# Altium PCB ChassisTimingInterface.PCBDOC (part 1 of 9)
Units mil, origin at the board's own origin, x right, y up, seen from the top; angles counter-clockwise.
Board outline 7007.87 x 4368.85 mil, 10 copper layers (Top Layer, Int1 (GND), Int2 (Sign), Int3 (Sign), Int4 (PWR), Int5 (GND), Int6 (Sign), Int7 (Sign), Int8 (GND), Bottom Layer), stack 54.89 mil thick; 537 components, 525 nets, 2288 pads, 1306 vias.
Unrouted connection lines stored in the file: 373.
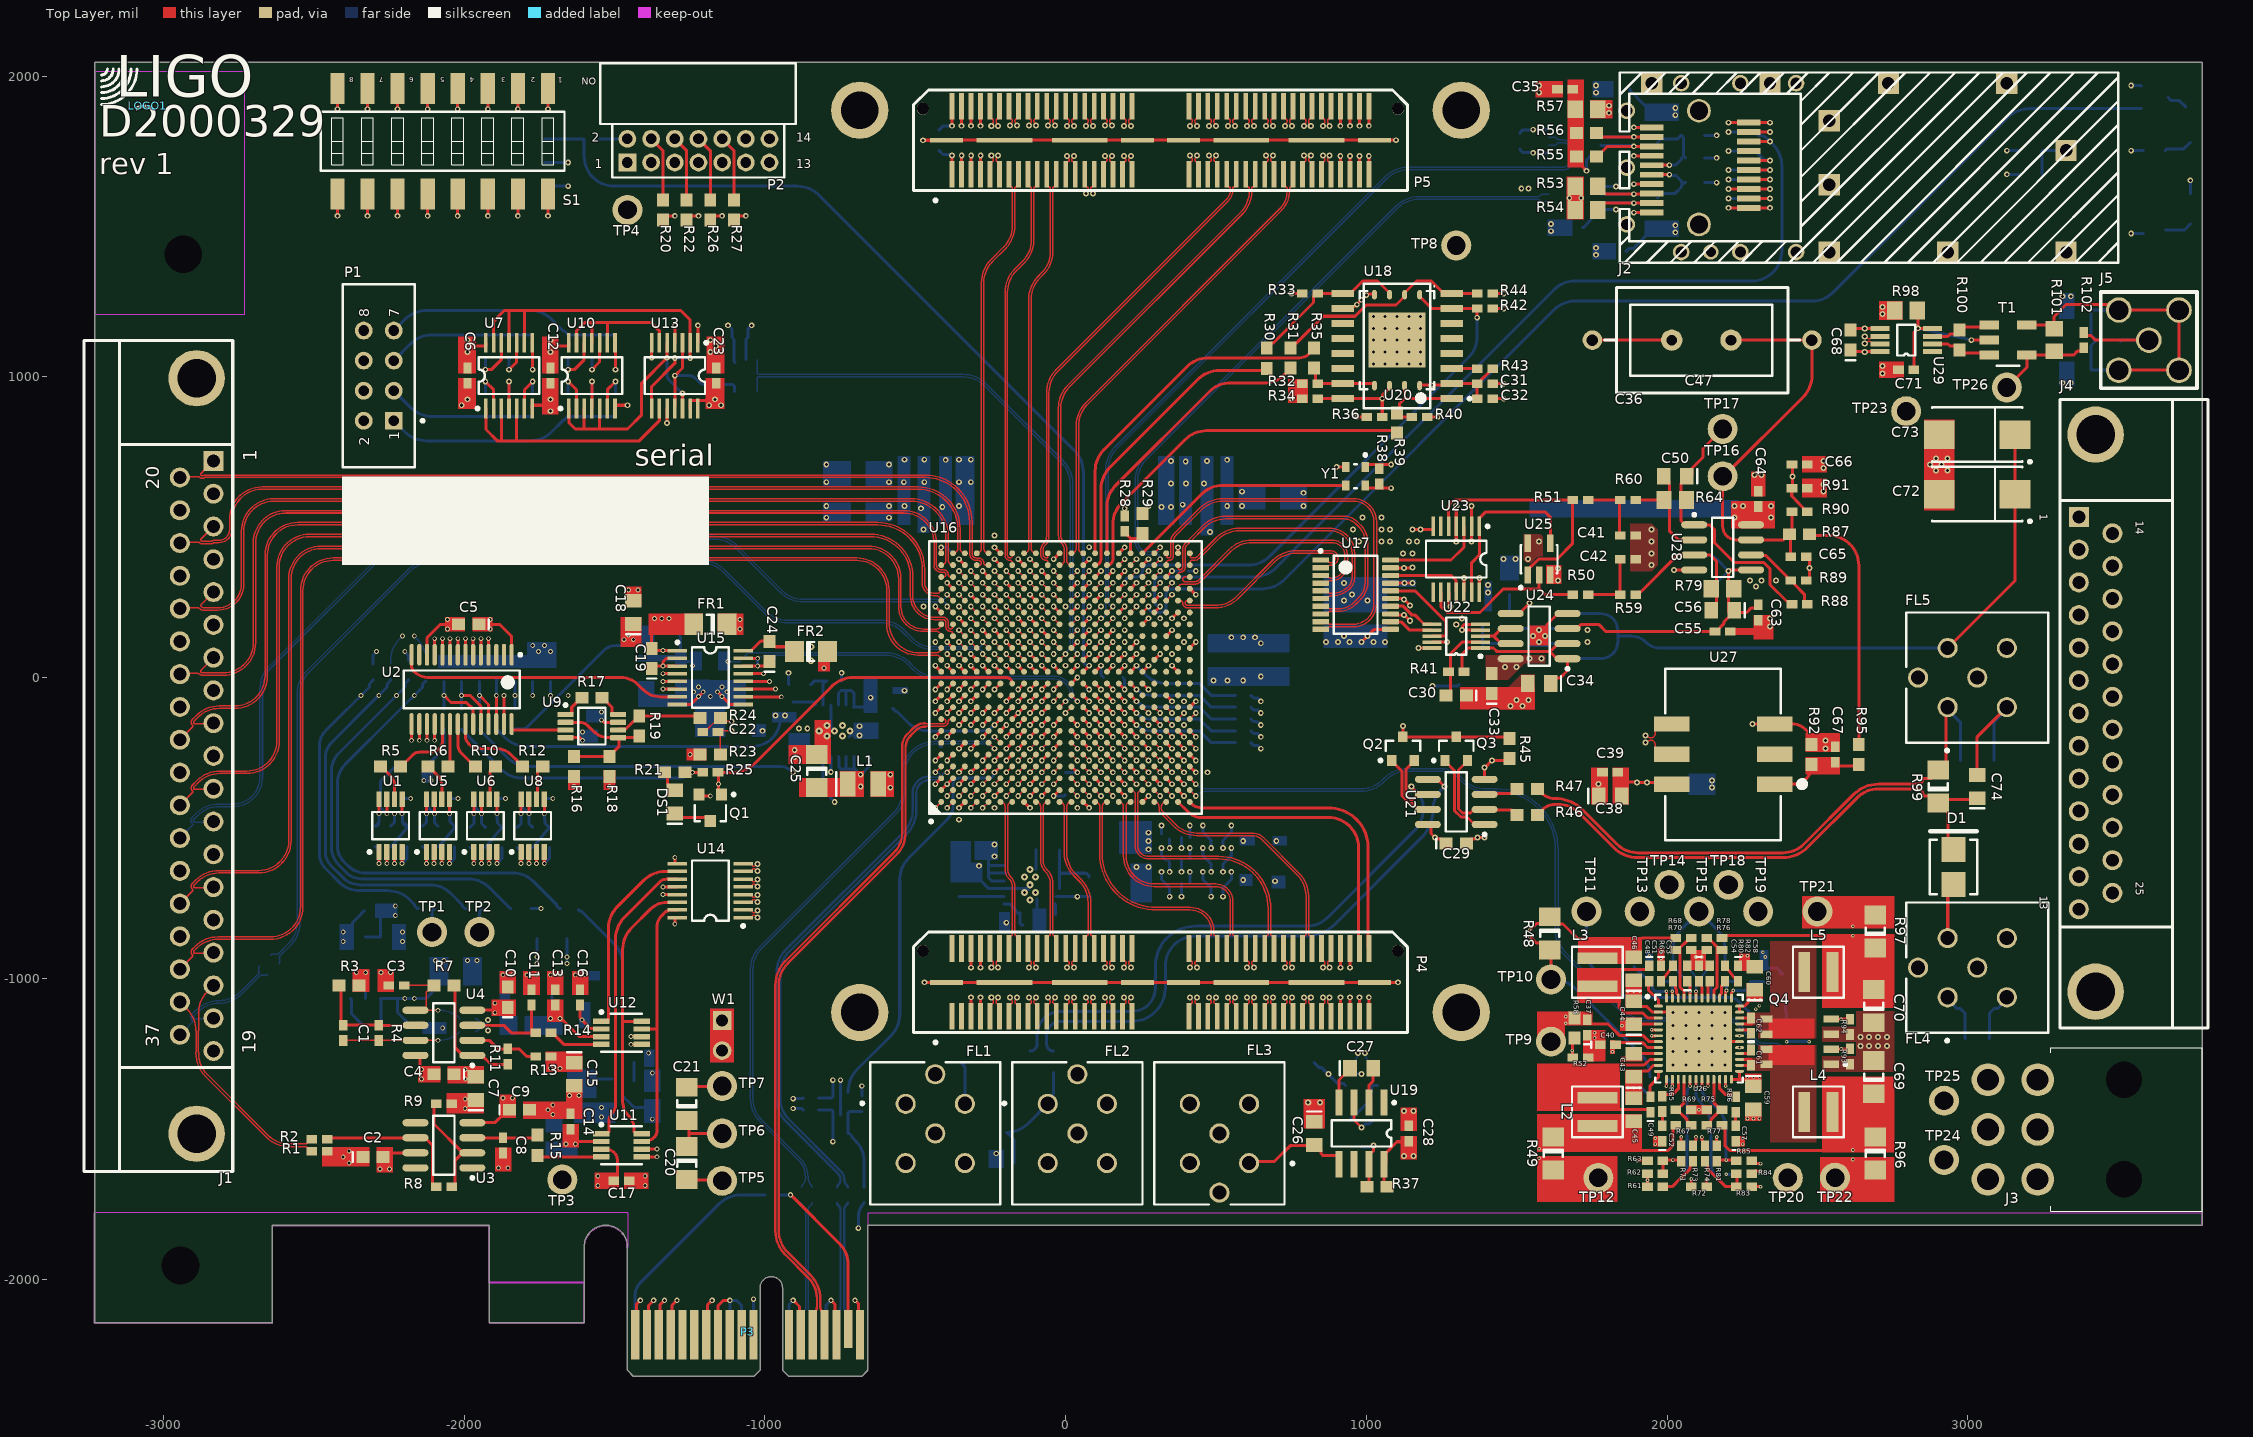
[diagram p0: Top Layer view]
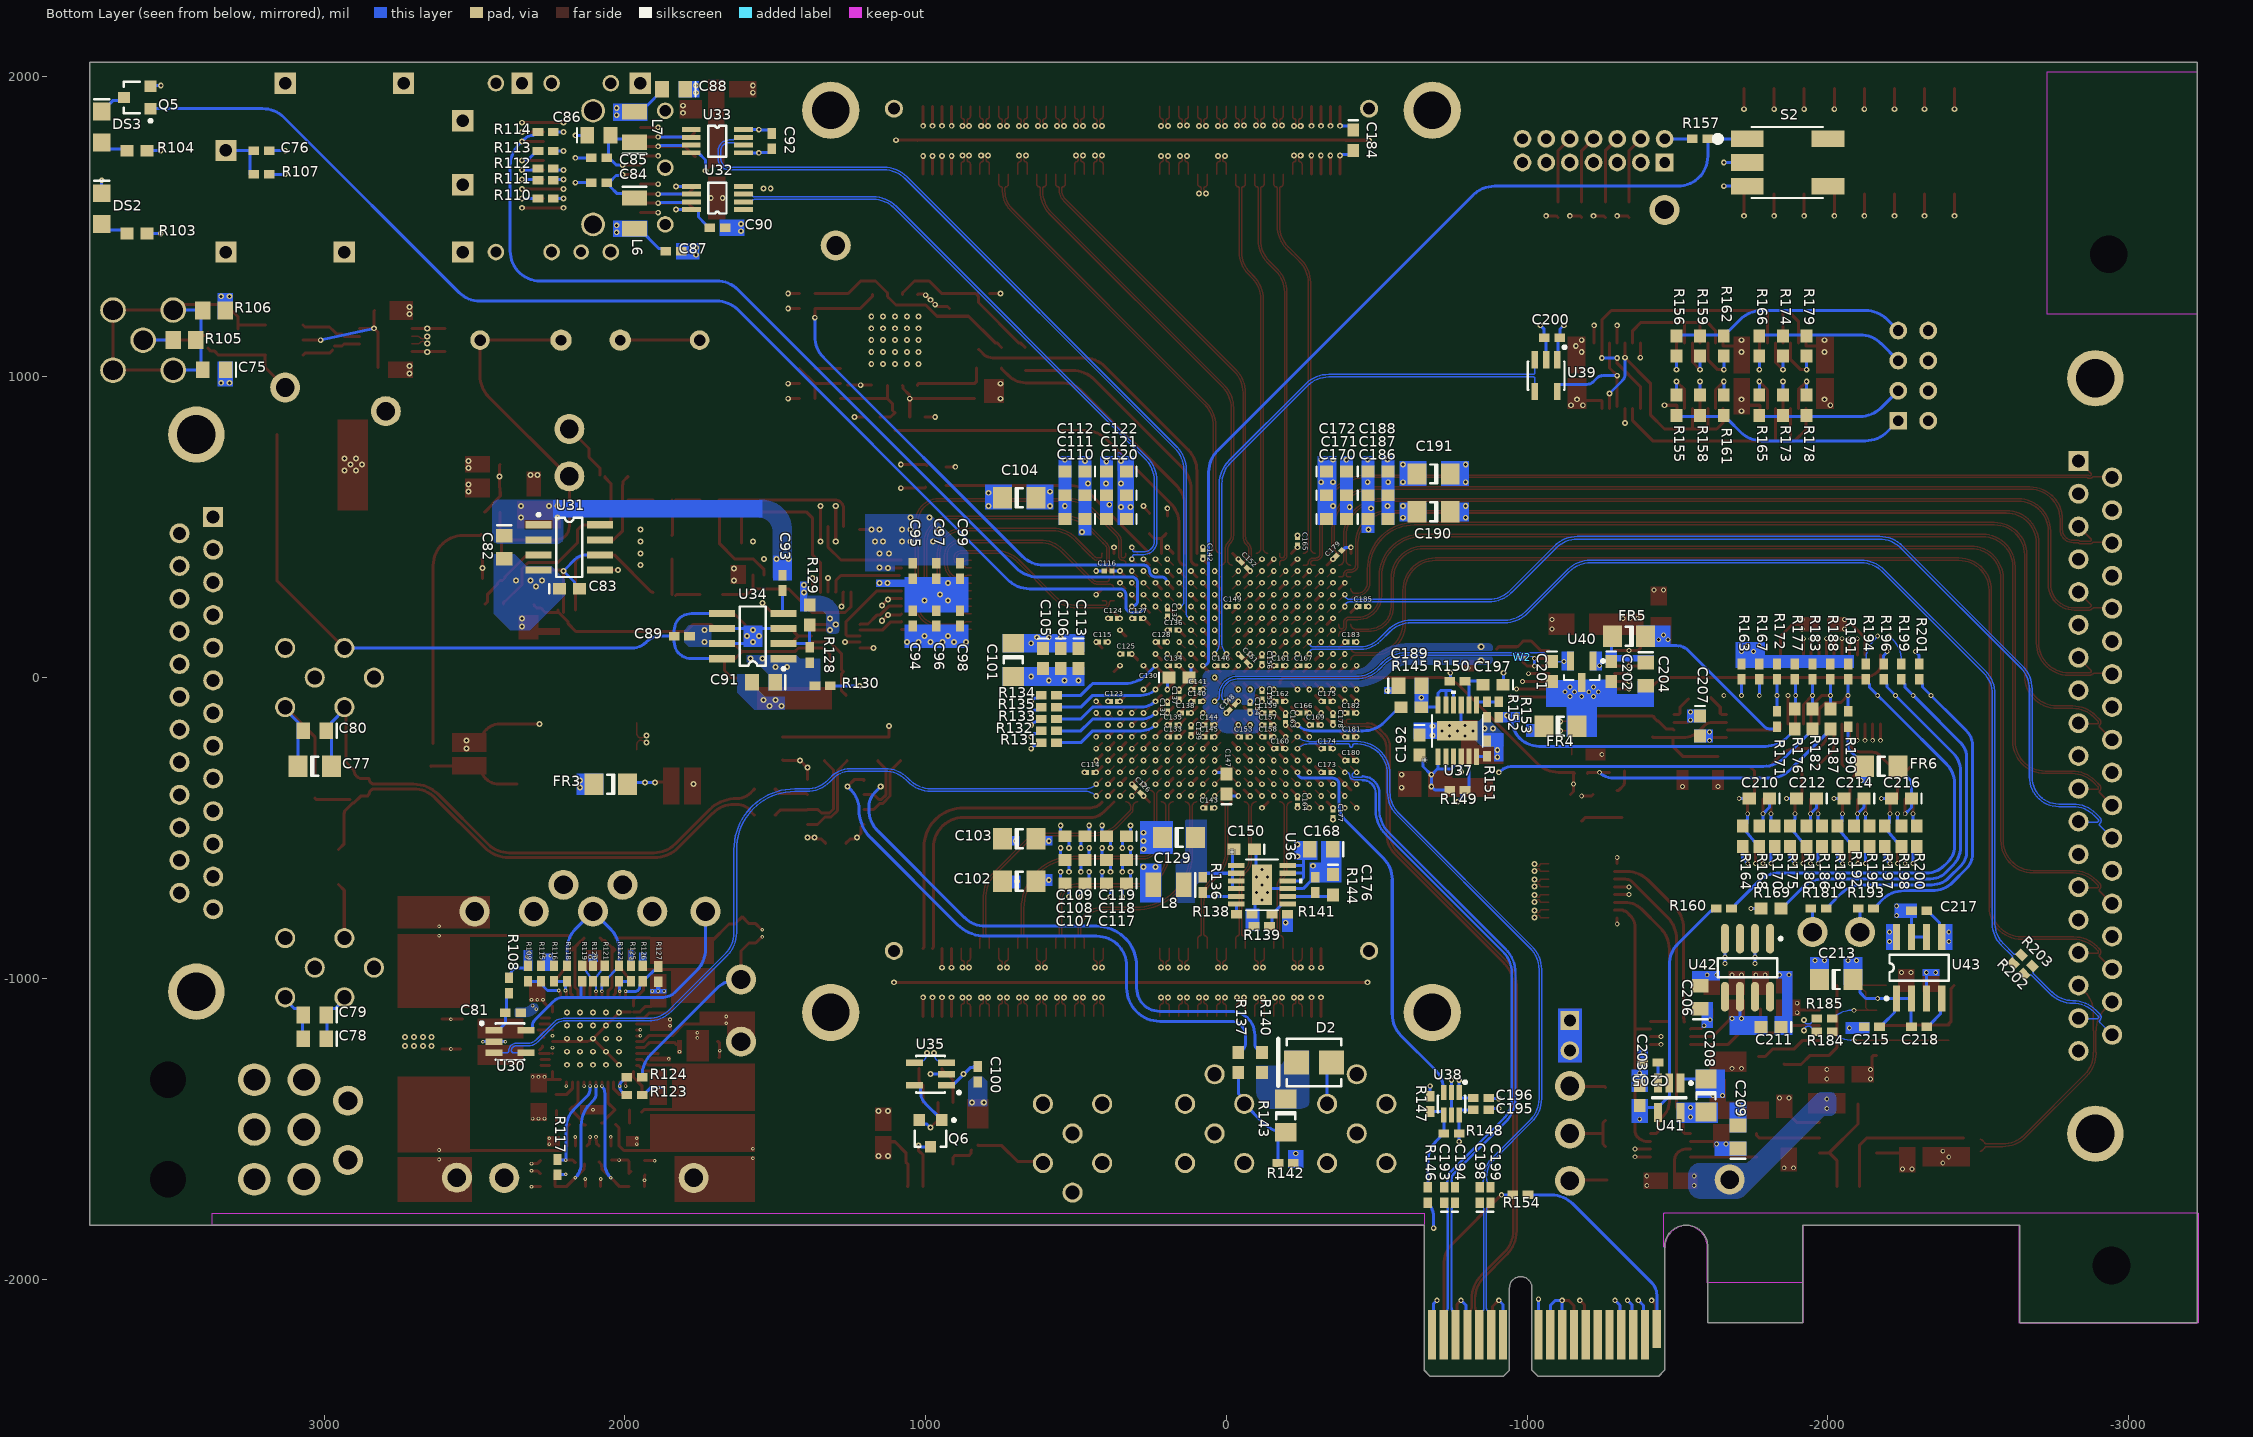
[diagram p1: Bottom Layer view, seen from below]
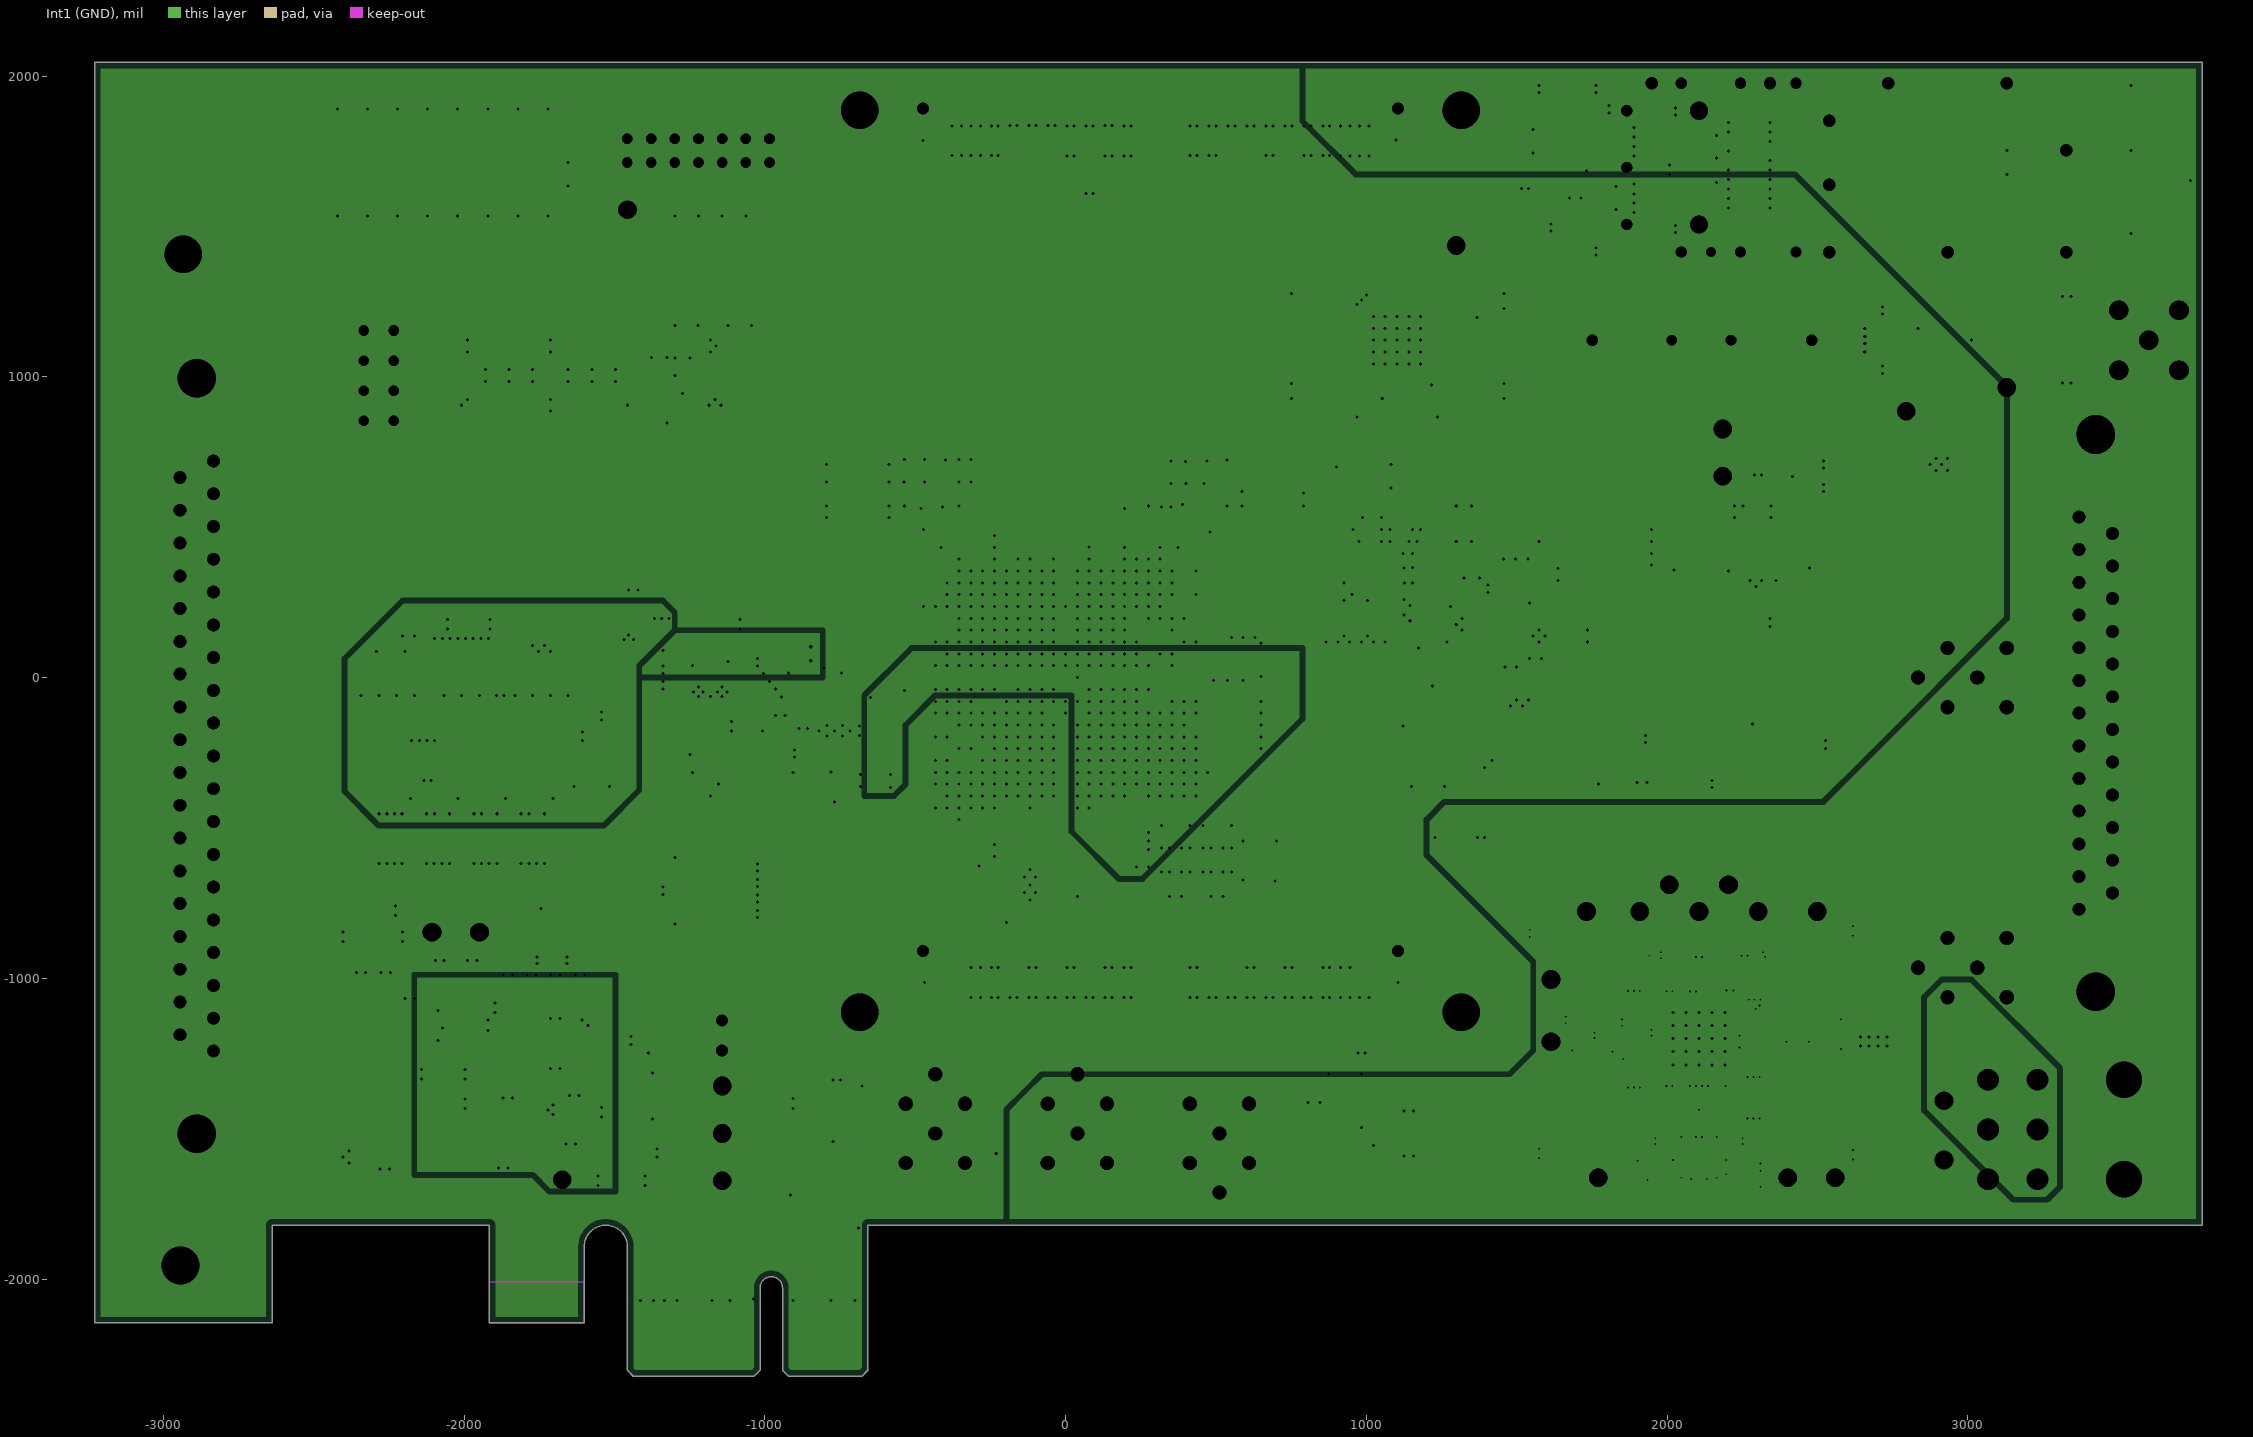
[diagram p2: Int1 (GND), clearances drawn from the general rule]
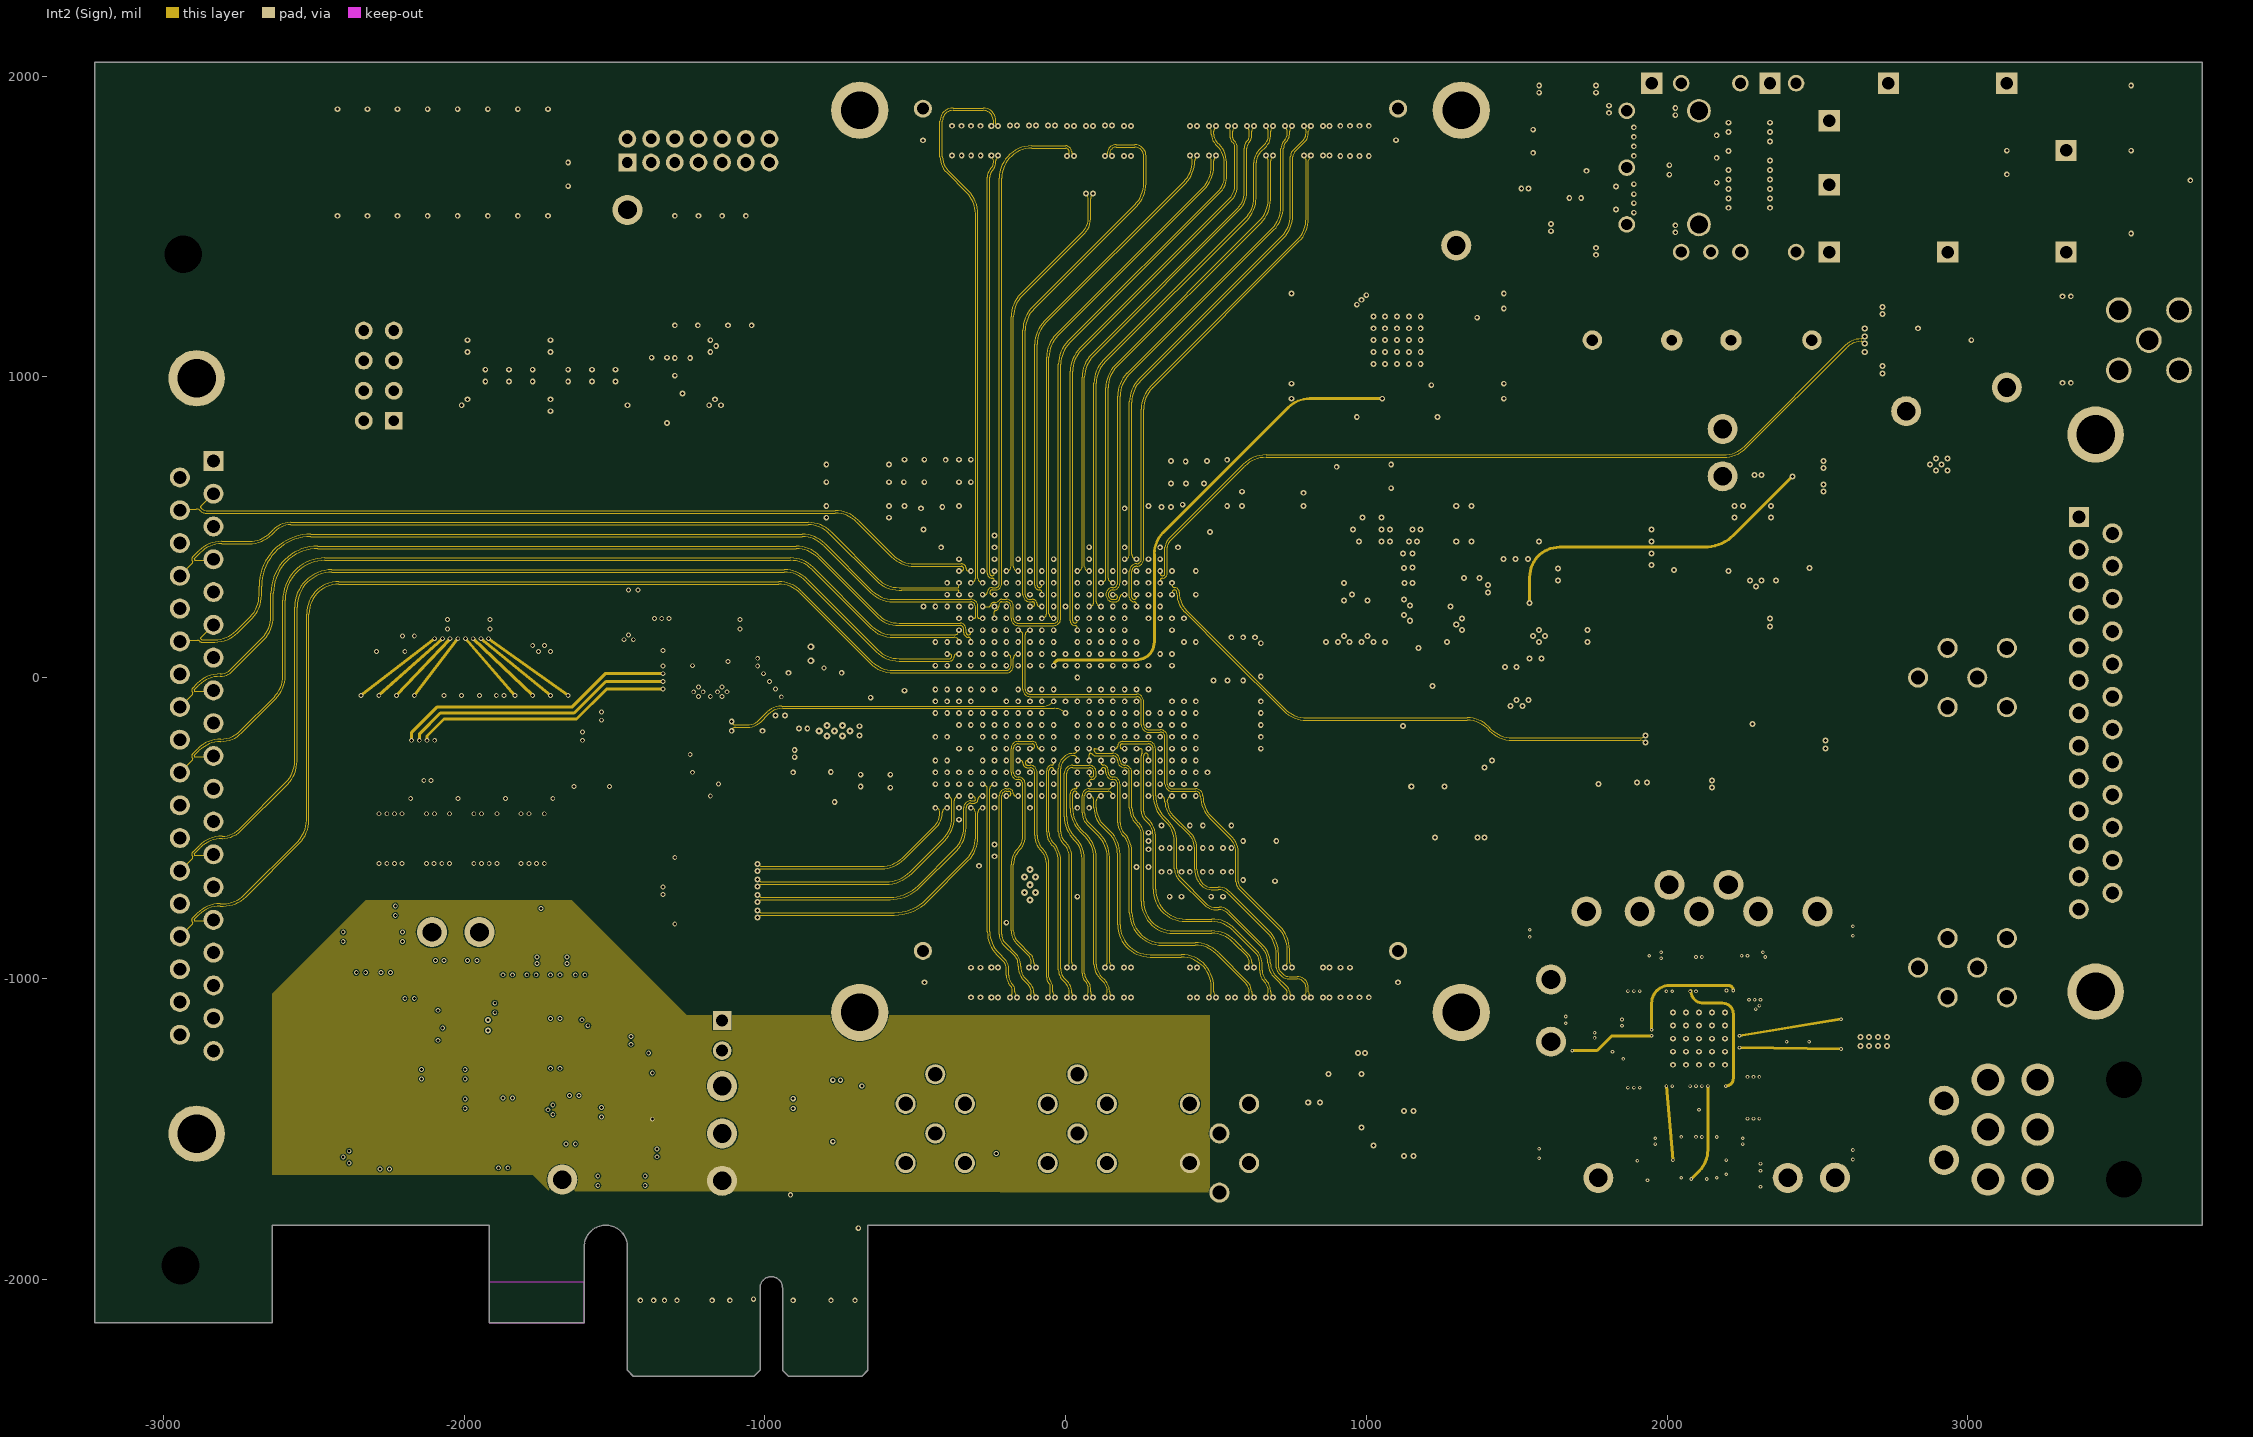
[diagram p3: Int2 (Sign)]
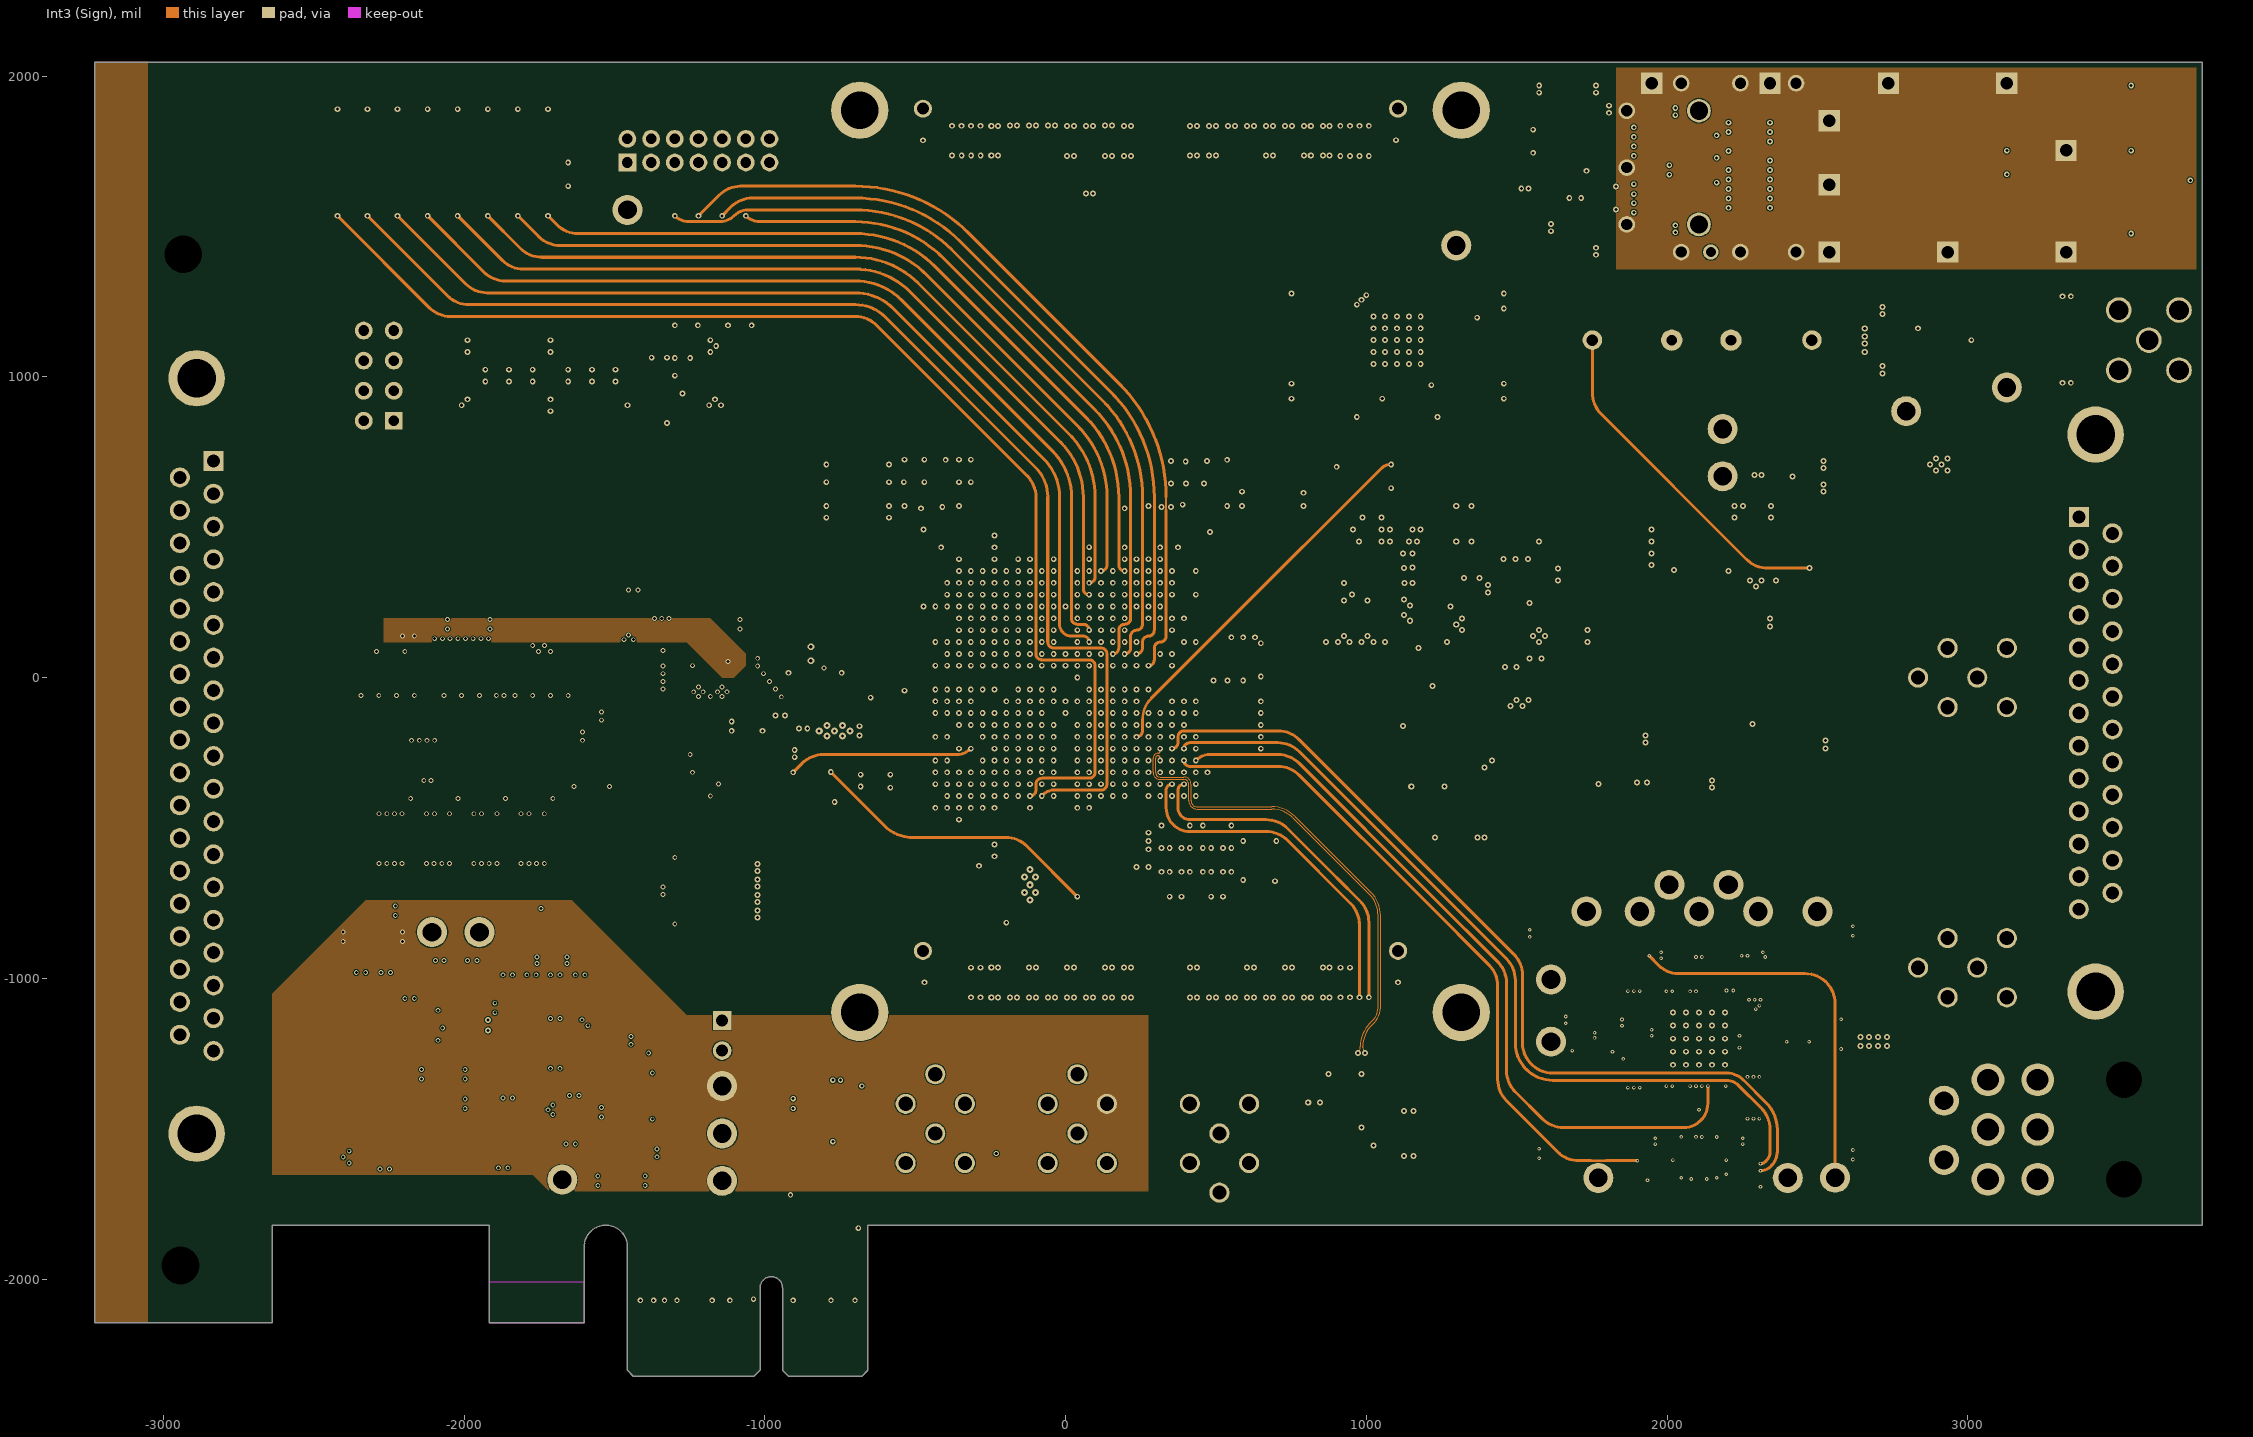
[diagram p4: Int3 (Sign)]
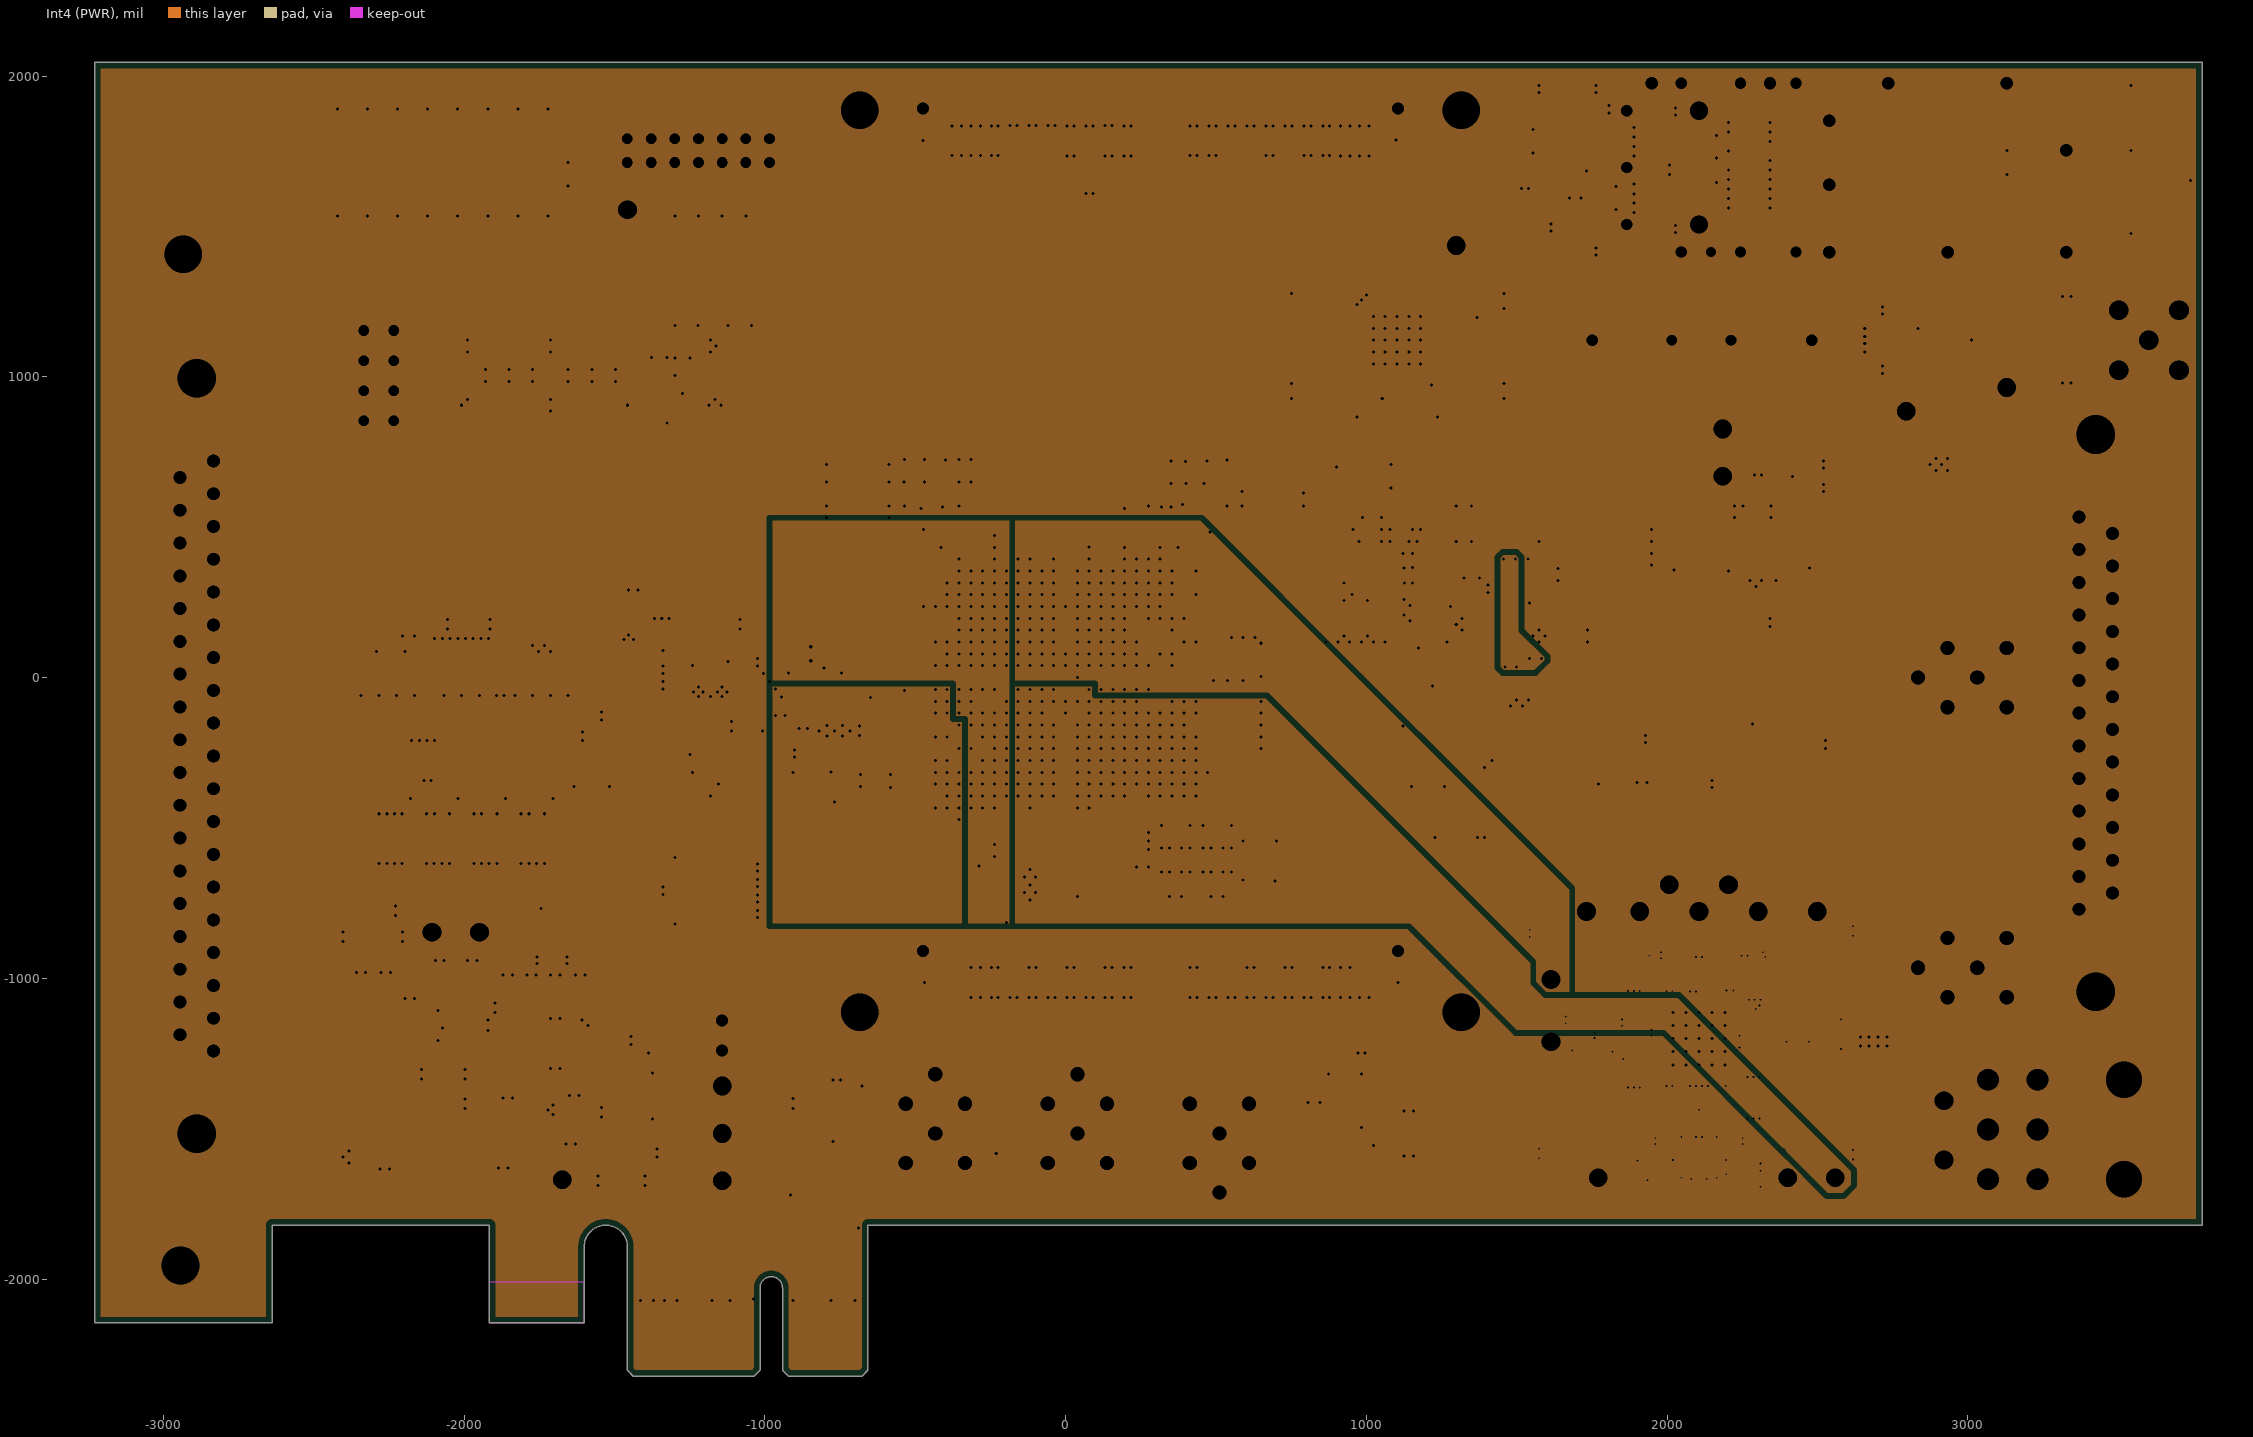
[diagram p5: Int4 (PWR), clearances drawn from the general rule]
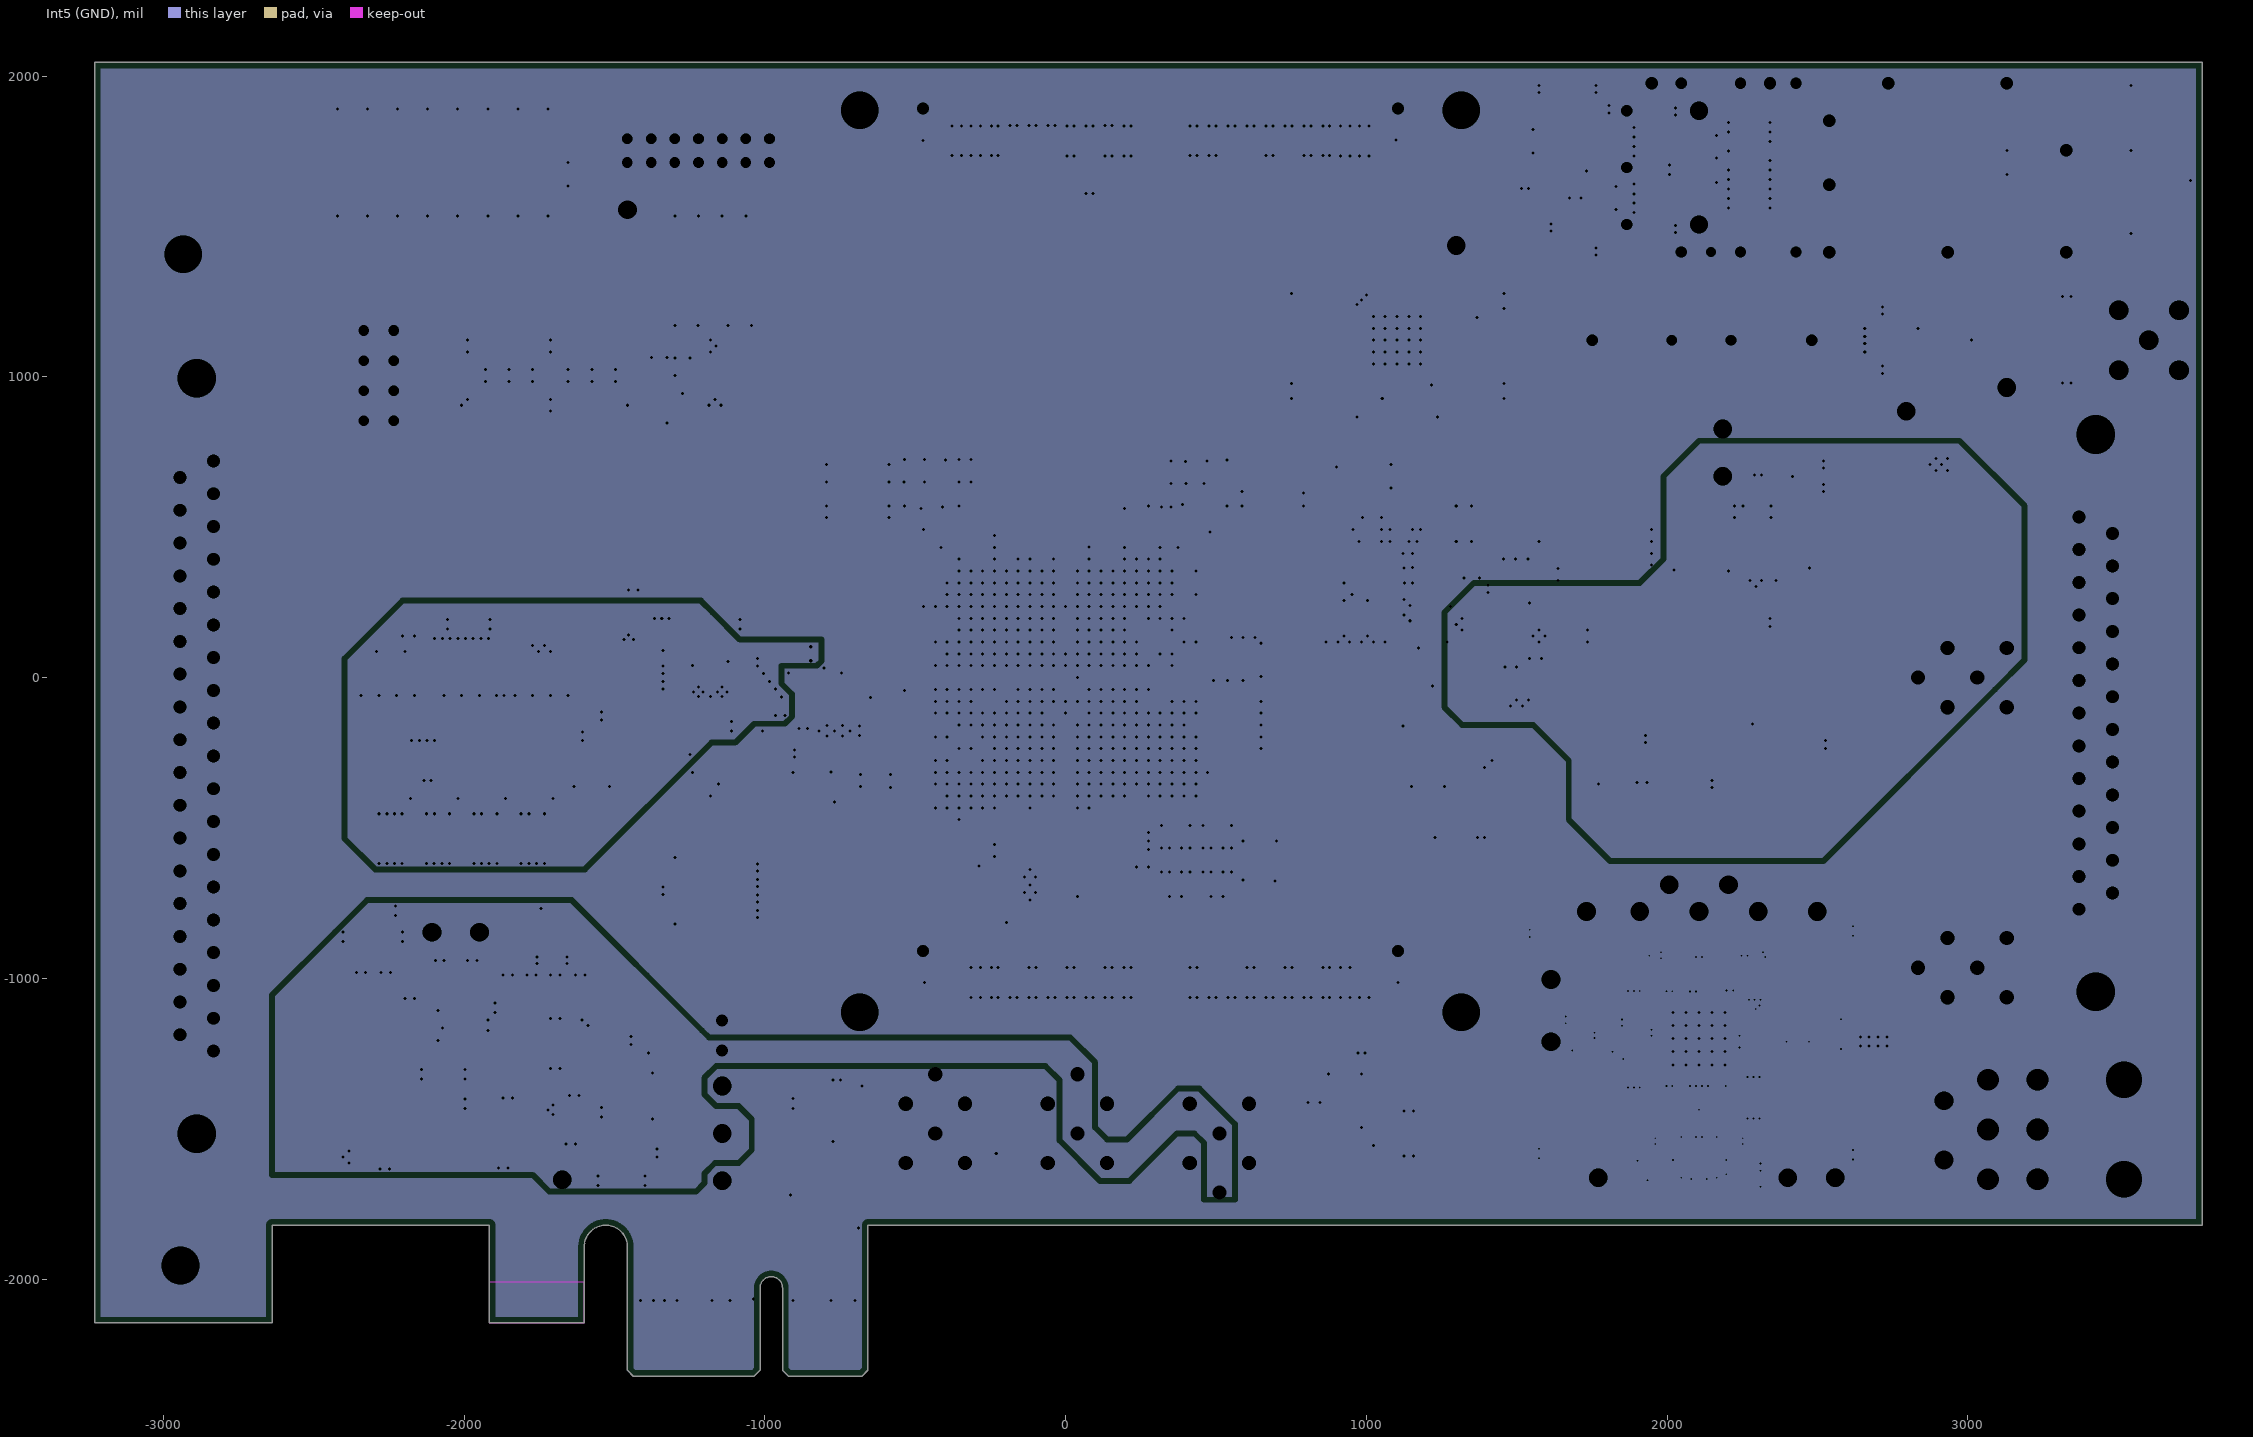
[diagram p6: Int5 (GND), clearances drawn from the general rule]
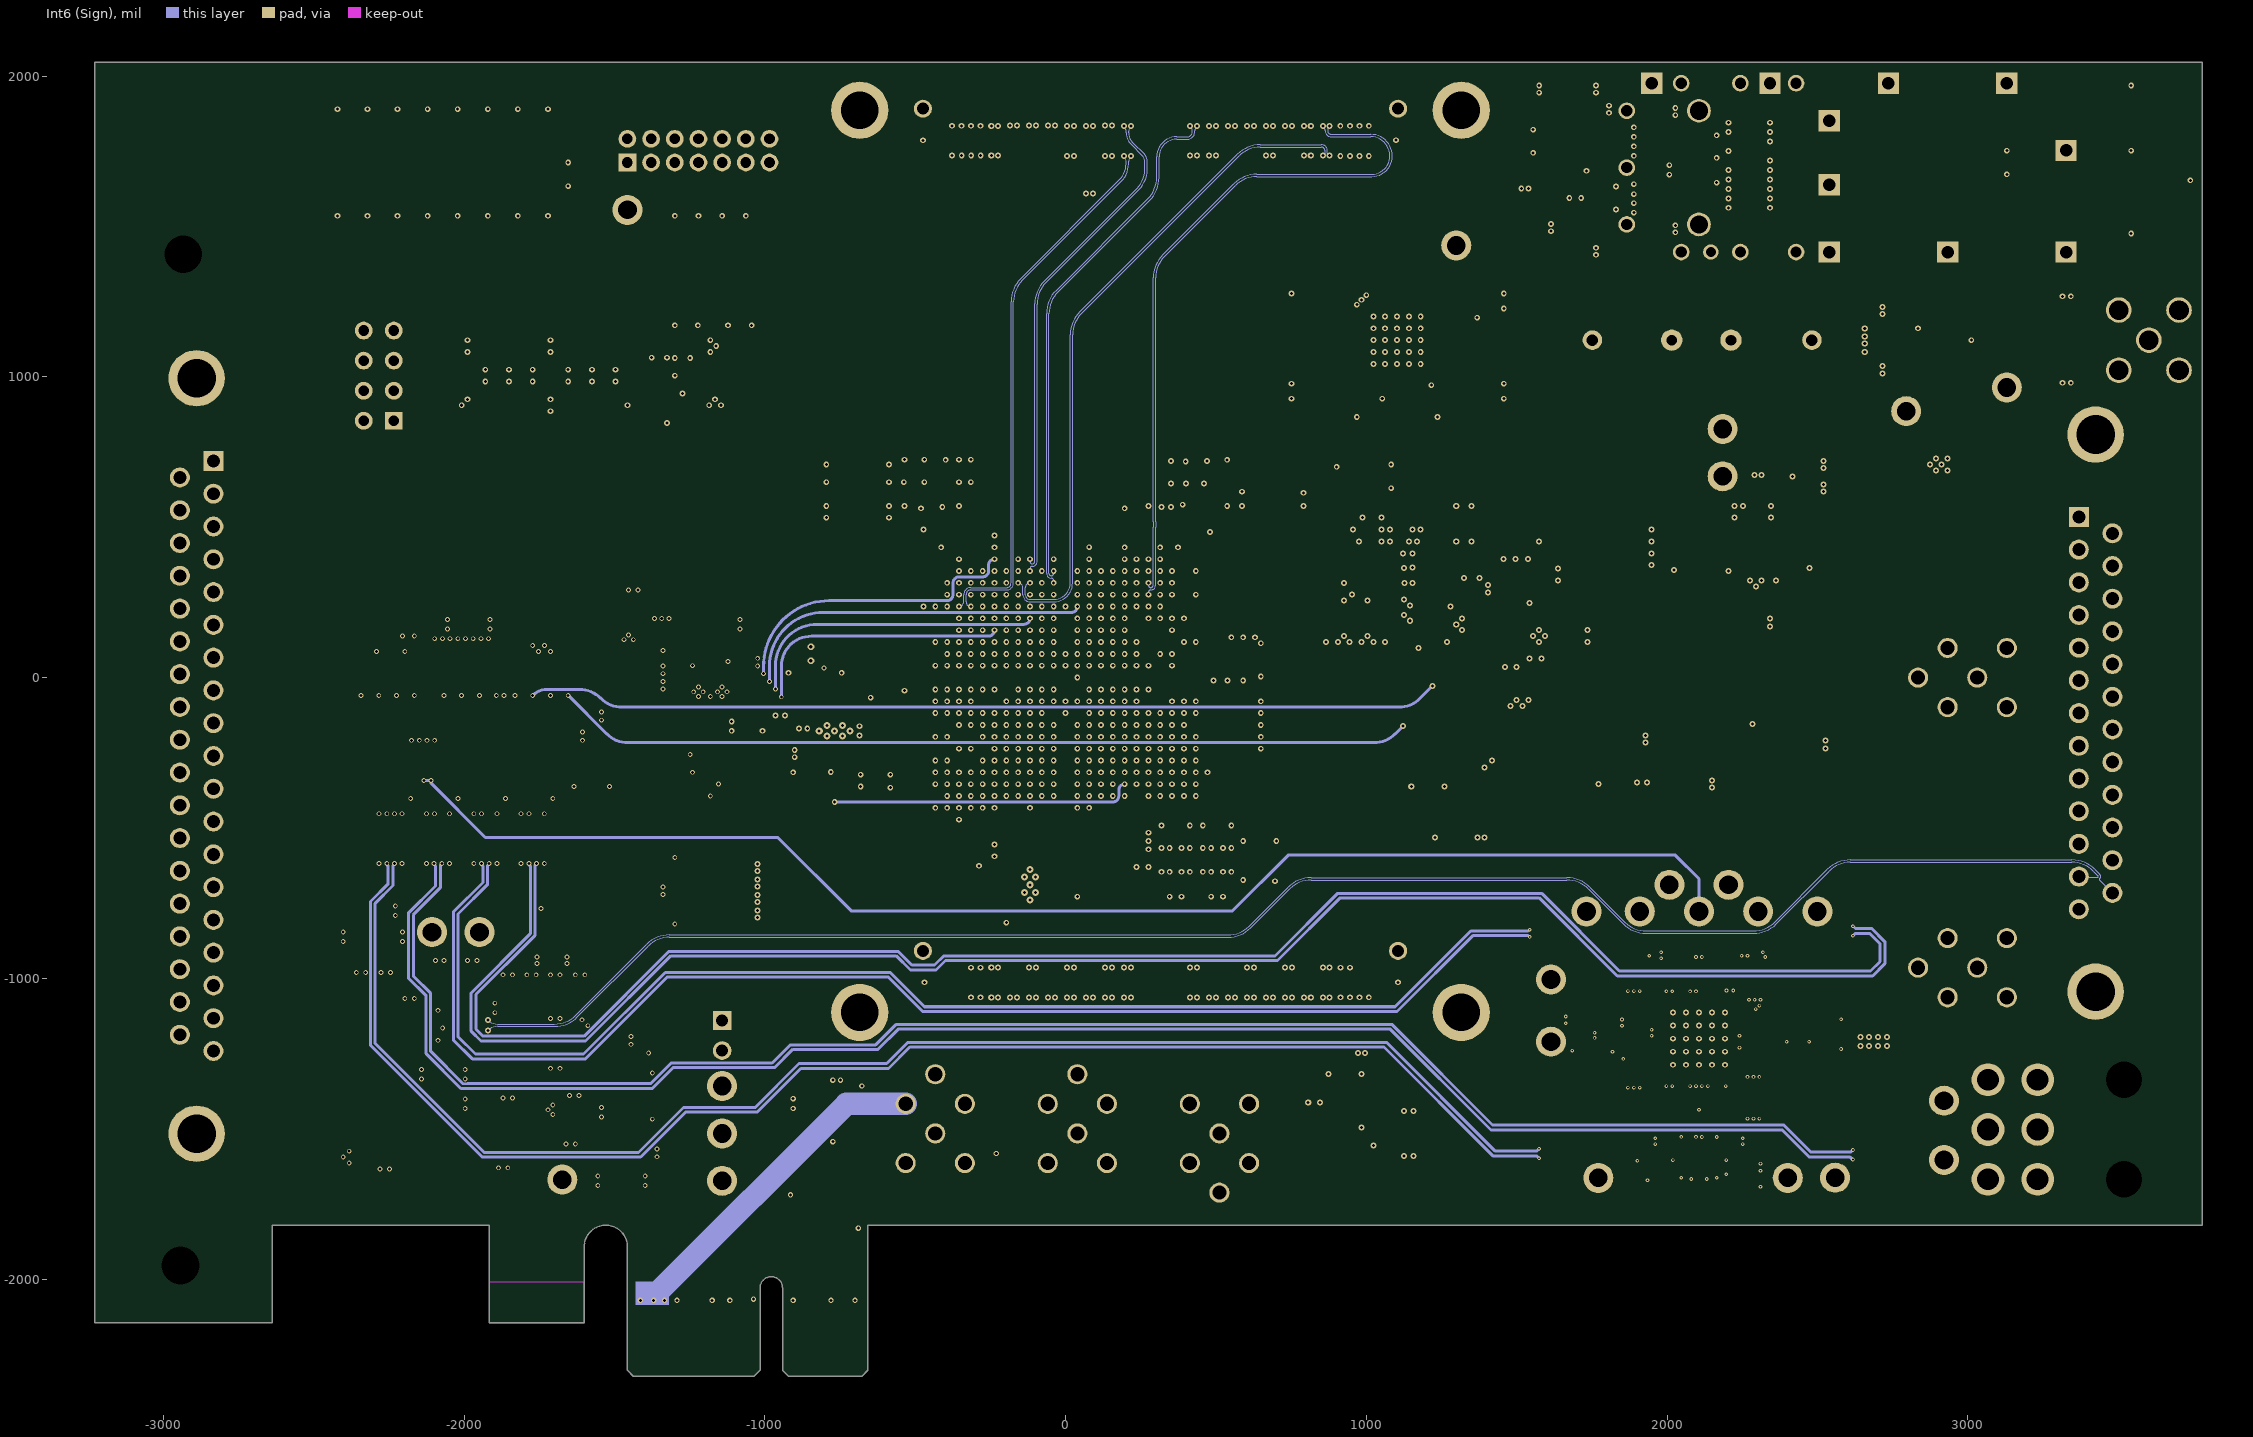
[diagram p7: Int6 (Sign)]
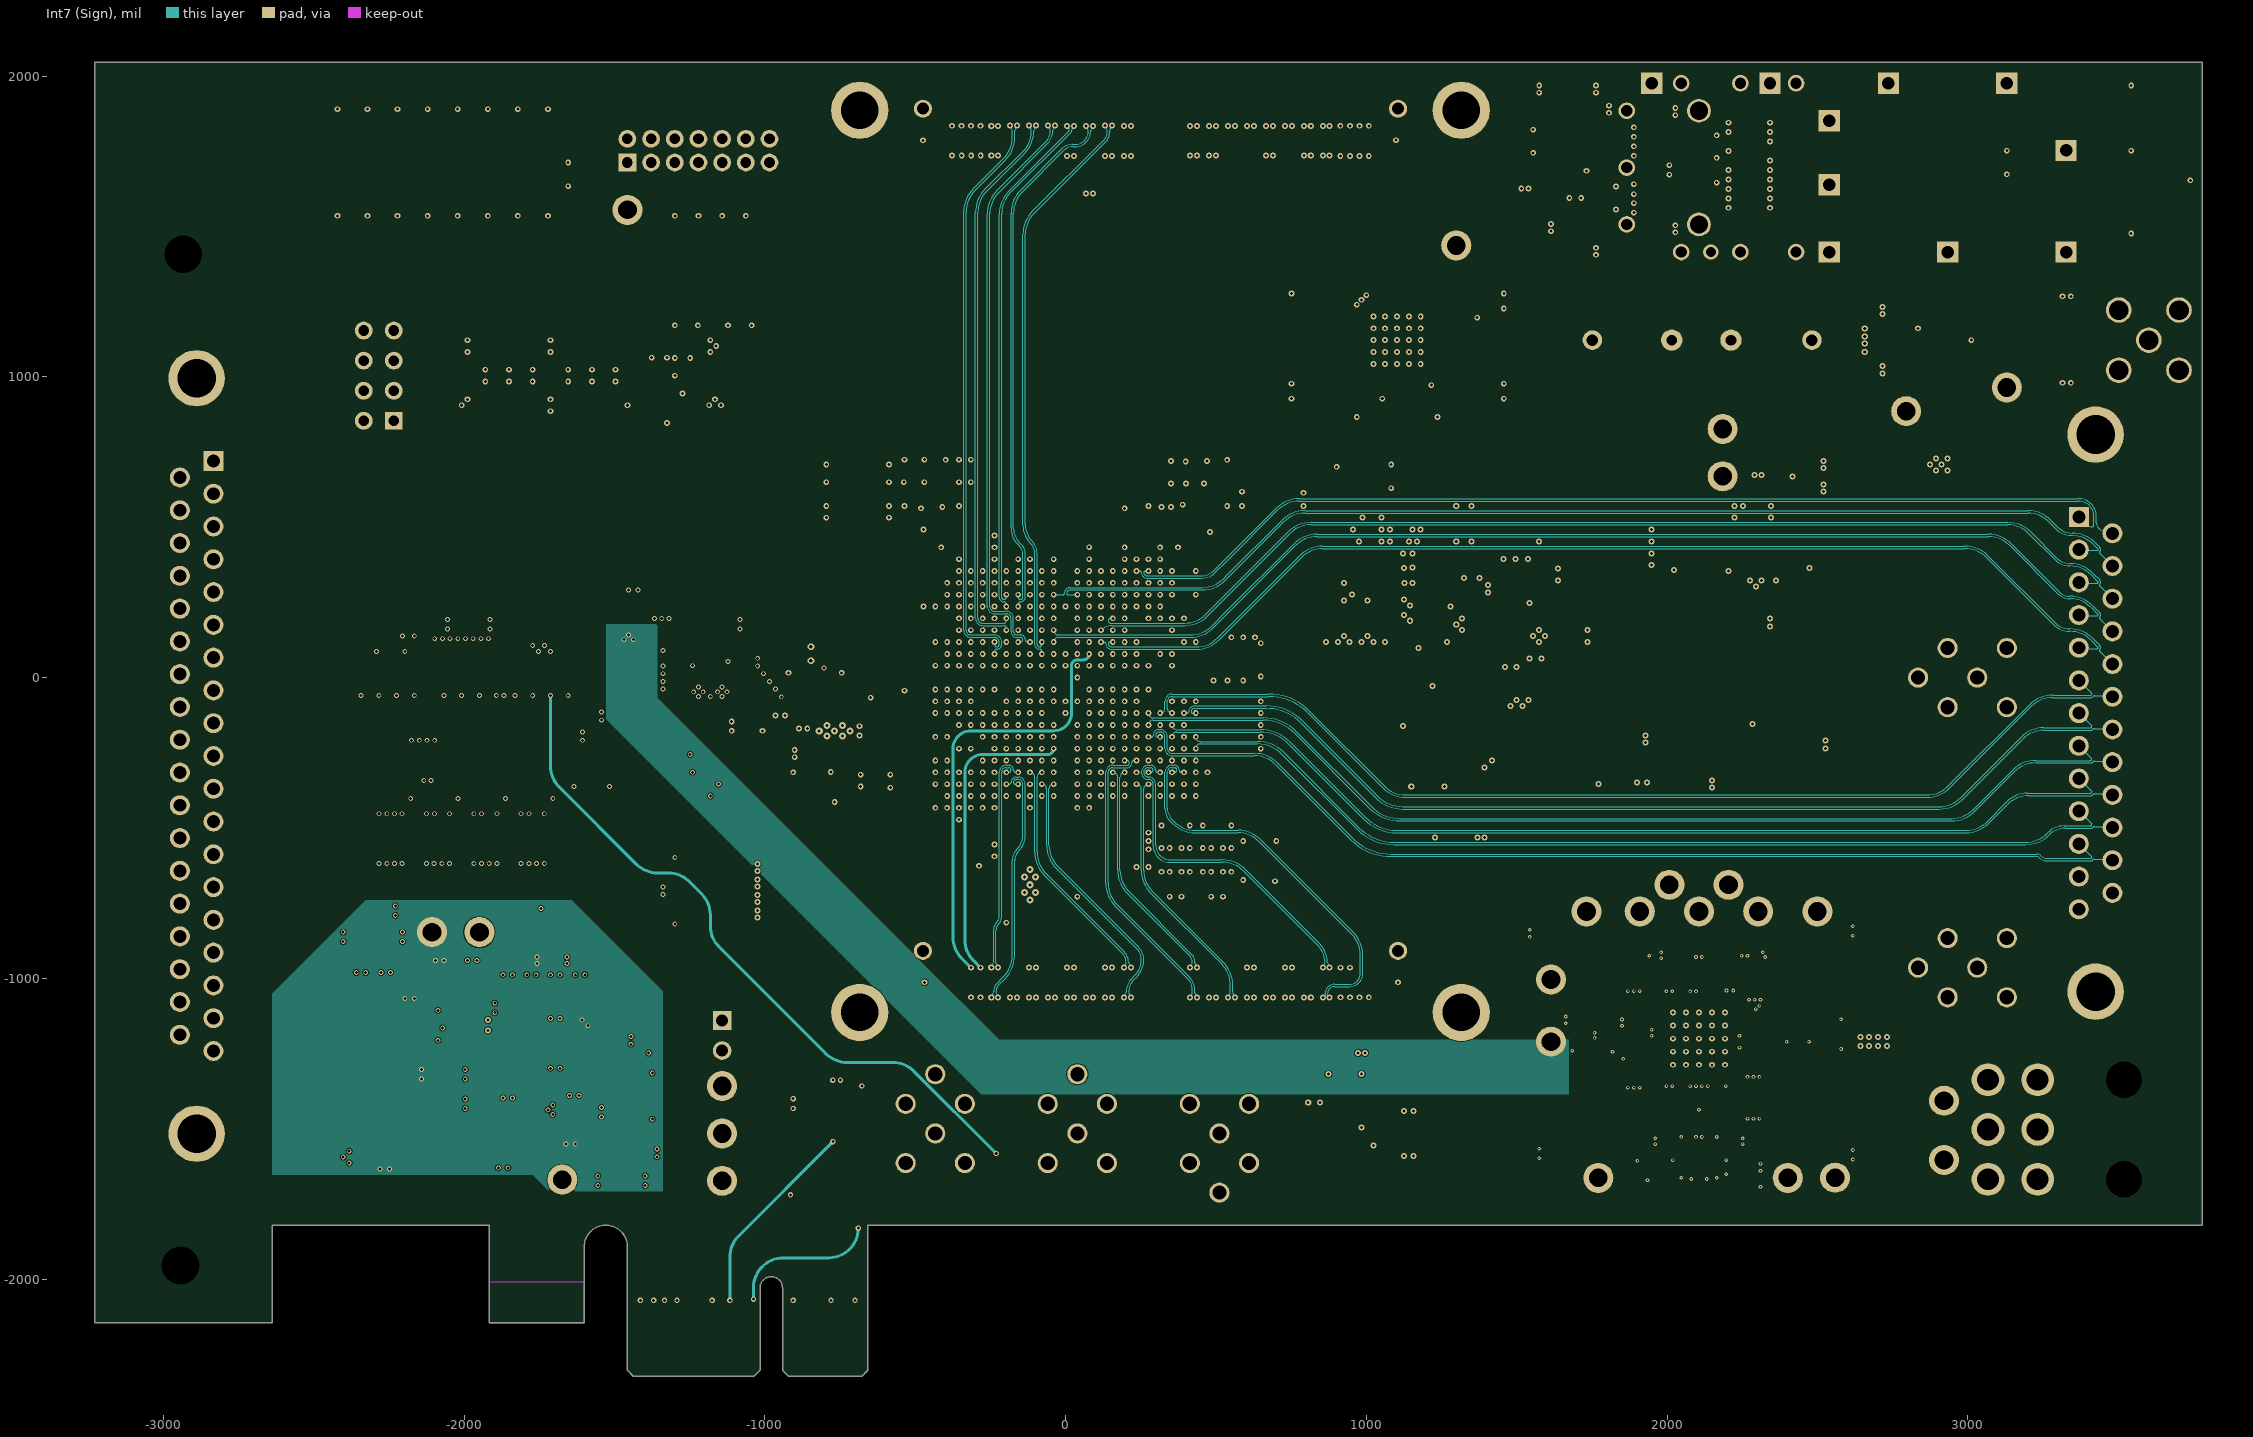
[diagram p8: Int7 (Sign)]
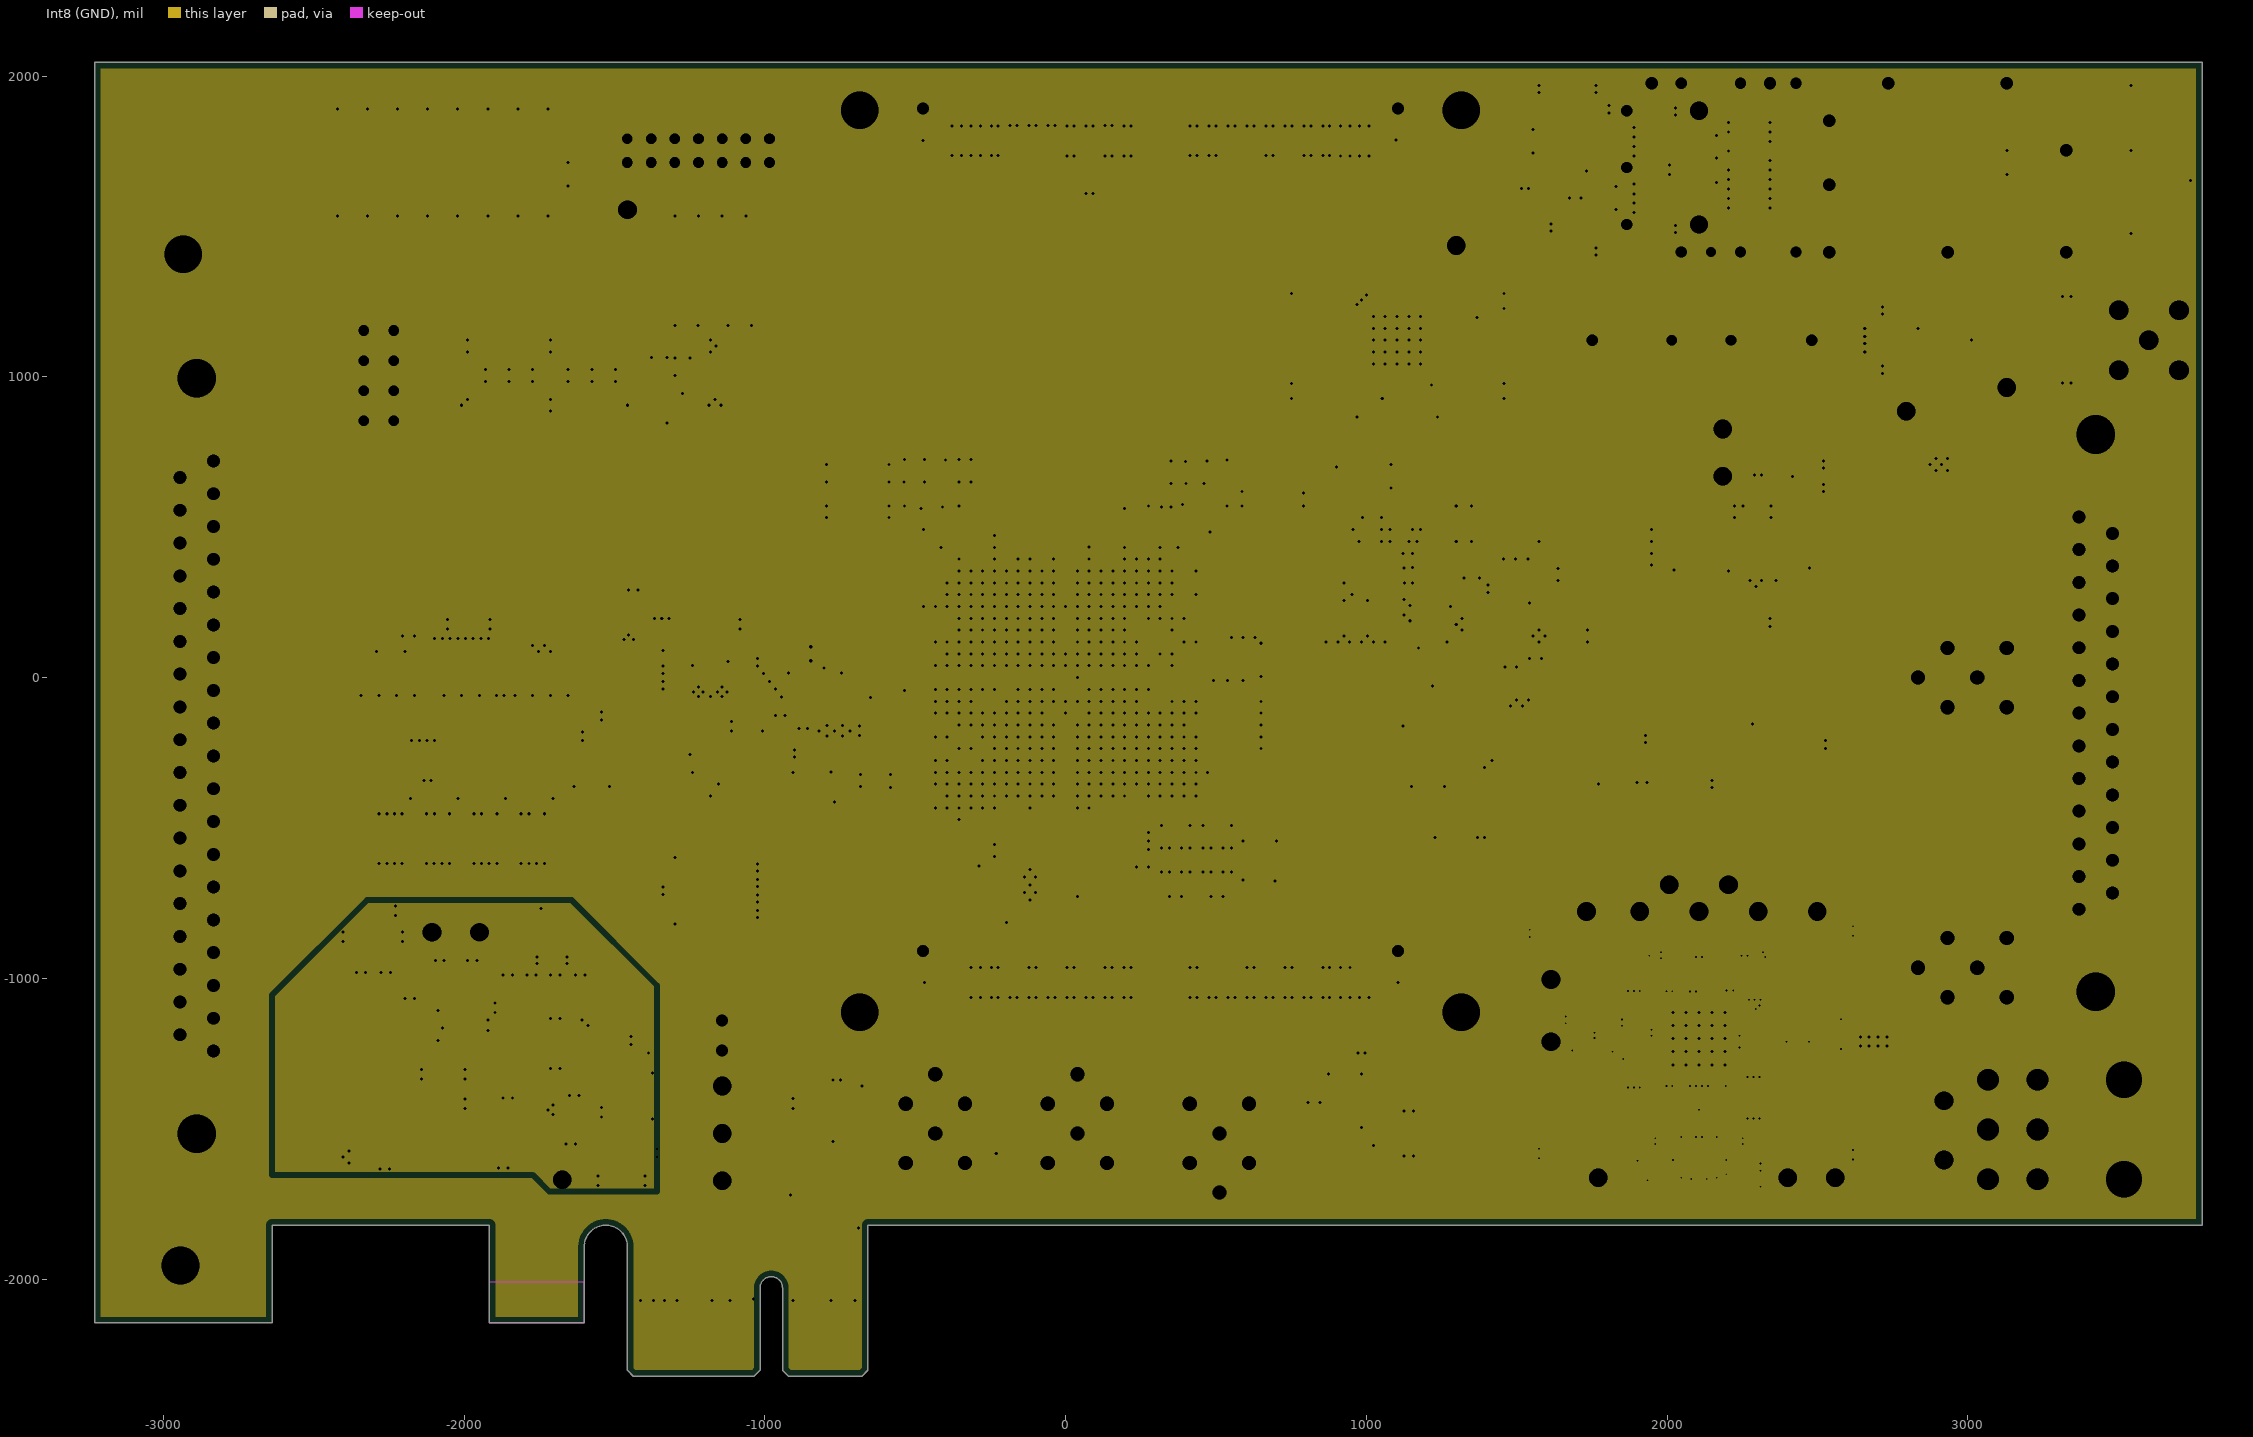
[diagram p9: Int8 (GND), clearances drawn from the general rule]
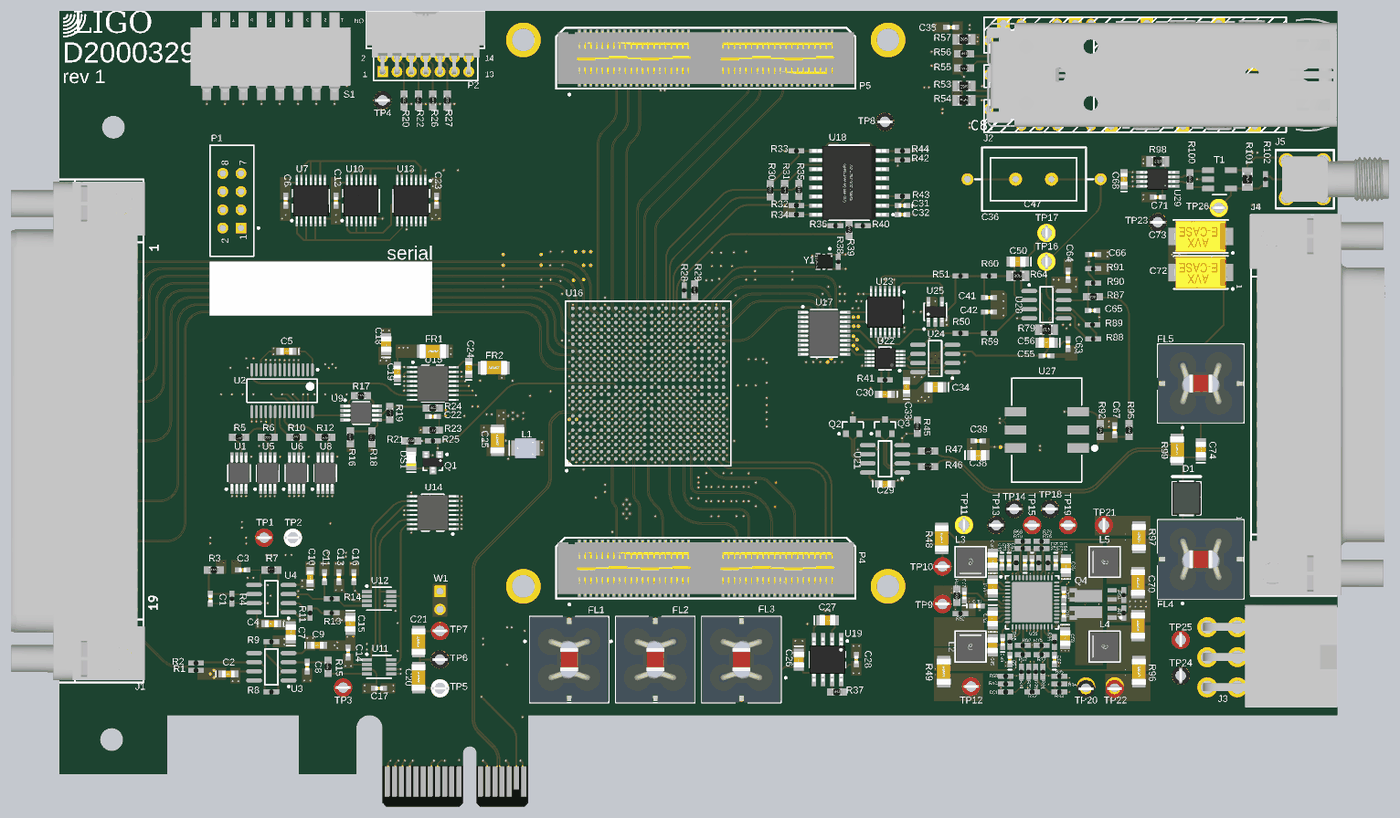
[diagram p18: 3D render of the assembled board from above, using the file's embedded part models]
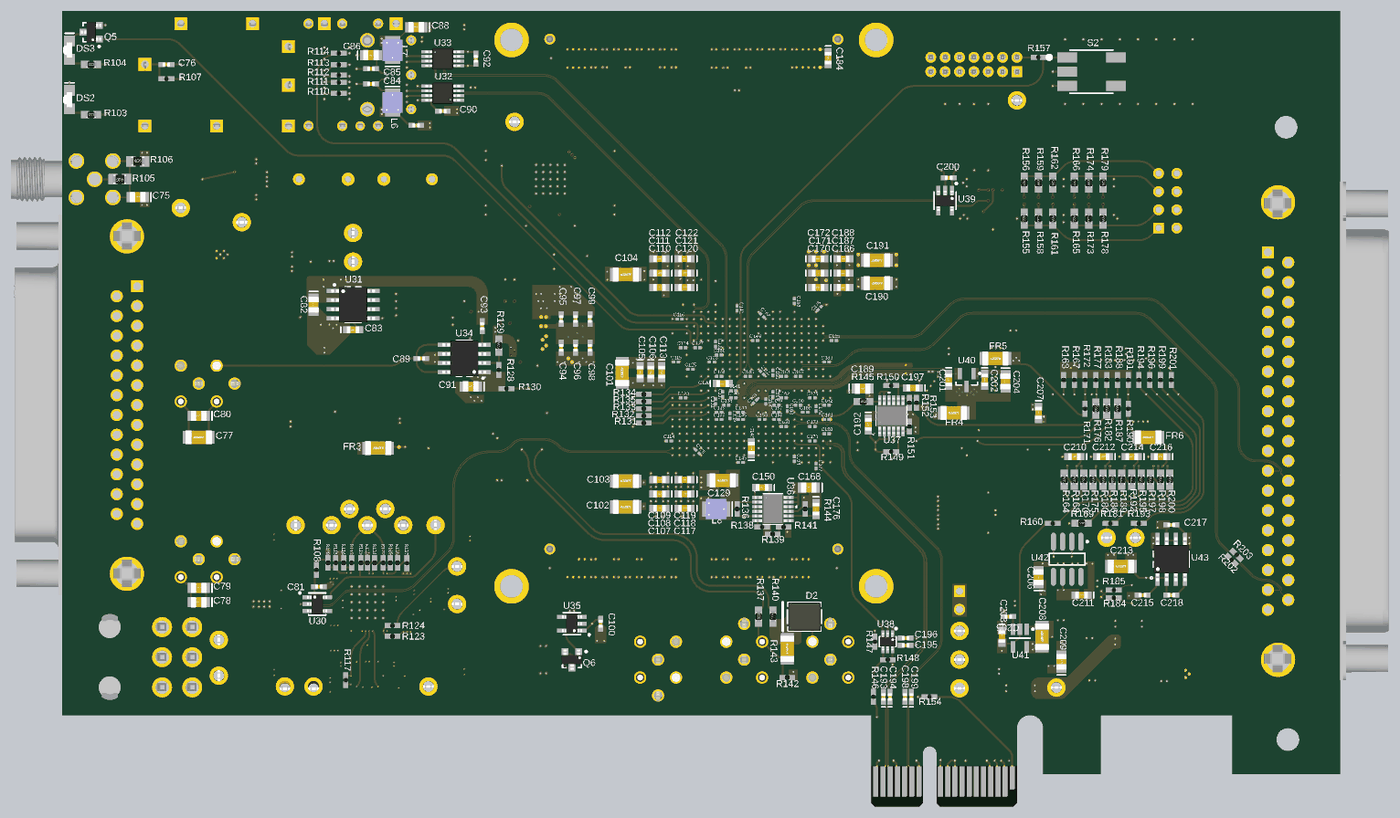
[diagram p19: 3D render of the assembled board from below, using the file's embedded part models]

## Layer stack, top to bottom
Top Solder: solder mask 1, SM-001, Dk 4
Top Layer: signal copper 0.689
Dielectric 1: prepreg 2.8, PP-006, Dk 4.1
Dielectric 2: prepreg 2.8, PP-006, Dk 4.1
Int1 (GND): plane copper 0.689, net (Multiple Nets)
Dielectric 3: core 5, Core-016, Dk 4.3
Int2 (Sign): signal copper 0.689
Dielectric 4: prepreg 2.8, PP-006, Dk 4.1
Dielectric 5: prepreg 2.8, PP-006, Dk 4.1
Int3 (Sign): signal copper 0.689
Dielectric 6: core 5, Core-016, Dk 4.3
Int4 (PWR): plane copper 0.689, net (Multiple Nets)
Dielectric 7: prepreg 2.8, PP-006, Dk 4.1
Dielectric 8: prepreg 2.8, PP-006, Dk 4.1
Int5 (GND): plane copper 0.689, net (Multiple Nets)
Dielectric 9: core 5, Core-016, Dk 4.3
Int6 (Sign): signal copper 0.689
Dielectric 10: prepreg 2.8, PP-006, Dk 4.1
Dielectric 11: prepreg 2.8, PP-006, Dk 4.1
Int7 (Sign): signal copper 0.689
Dielectric 12: core 5, Core-016, Dk 4.3
Int8 (GND): plane copper 0.689, net VDD
Dielectric 13: prepreg 2.8, PP-006, Dk 4.1
Dielectric 14: prepreg 2.8, PP-006, Dk 4.1
Bottom Layer: signal copper 0.689
Bottom Solder: solder mask 1, SM-001, Dk 4

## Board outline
-3228.35,-2145.67 -2637.8,-2145.67 -2637.8,-1820.87 -1915.35,-1820.87 -1915.35,-2145.67 -1600.39,-2145.67 -1600.39,-1892.72 cw(c-1528.54,-1892.72) -1456.69,-1892.72 -1456.69,-2303.15 -1437.01,-2322.83 -1035.43,-2322.83 -1015.75,-2303.15 -1015.75,-2029.53 cw(c-978.35,-2029.53) -940.94,-2029.53 -940.94,-2303.15 -921.26,-2322.83 -677.17,-2322.83 -657.48,-2303.15 -657.48,-1820.87 3779.53,-1820.87 3779.53,2046.01 -3228.35,2046.01

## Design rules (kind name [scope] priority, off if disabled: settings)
Clearance [All] p1: gap=3 ignorepadtopadclearanceinfootprint=FALSE
DiffPairsRouting DiffPairsRouting_BGA [WithinRoom('FPGA')] p1: maxlimit=5 minlimit=3 mostfreqgap=5 toplayer_maxgap=3 toplayer_prefgap=3 toplayer_minwidth=5 toplayer_maxwidth=5 toplayer_prefwidth=5 midlayer3_mingap=5 midlayer3_minwidth=3 midlayer3_maxwidth=3 midlayer3_prefwidth=3 midlayer4_mingap=5 midlayer4_minwidth=3 midlayer4_maxwidth=3 midlayer4_prefwidth=3 midlayer5_mingap=5 midlayer5_minwidth=3 midlayer5_maxwidth=3 midlayer5_prefwidth=3 midlayer6_mingap=5 midlayer6_minwidth=3 midlayer6_maxwidth=3 midlayer6_prefwidth=3 bottomlayer_maxgap=3 bottomlayer_prefgap=3 bottomlayer_minwidth=5 bottomlayer_maxwidth=5 bottomlayer_prefwidth=5 maxuncoupledlength=5
DiffPairsRouting DiffPairsRouting_PCIe_RX0 [InDifferentialPair('PCIE.PCIE_RX0')] p2: maxlimit=5 minlimit=3 mostfreqgap=3 toplayer_maxgap=3.1 toplayer_minwidth=5 toplayer_maxwidth=9.06 toplayer_prefwidth=8 midlayer3_minwidth=3 midlayer3_maxwidth=3.66 midlayer3_prefwidth=3.5 midlayer4_minwidth=3 midlayer4_maxwidth=3.66 midlayer4_prefwidth=3.5 midlayer5_minwidth=3 midlayer5_maxwidth=3.66 midlayer5_prefwidth=3.5 midlayer6_minwidth=3 midlayer6_maxwidth=3.66 midlayer6_prefwidth=3.5 bottomlayer_maxgap=3.1 bottomlayer_minwidth=5 bottomlayer_maxwidth=9.06 bottomlayer_prefwidth=8 impedanceprofiledriven=TRUE impedanceprofileid={3B99ABB2-9DB6-41AF-ADEC-26CBF4FD55D9} impedanceprofilevalue=85.000000 maxuncoupledlength=500
DiffPairsRouting DiffPairsRouting_PCIe_PER0 [InDifferentialPair('PER0')] p3: maxlimit=5 minlimit=3 mostfreqgap=3 toplayer_maxgap=3.1 toplayer_minwidth=5 toplayer_maxwidth=9 toplayer_prefwidth=8 midlayer3_minwidth=3 midlayer3_maxwidth=3.5 midlayer3_prefwidth=3.5 midlayer4_minwidth=3 midlayer4_maxwidth=3.5 midlayer4_prefwidth=3.5 midlayer5_minwidth=3 midlayer5_maxwidth=3.5 midlayer5_prefwidth=3.5 midlayer6_minwidth=3 midlayer6_maxwidth=3.5 midlayer6_prefwidth=3.5 bottomlayer_maxgap=3.1 bottomlayer_minwidth=5 bottomlayer_maxwidth=9 bottomlayer_prefwidth=8 impedanceprofiledriven=TRUE impedanceprofileid={3B99ABB2-9DB6-41AF-ADEC-26CBF4FD55D9} impedanceprofilevalue=85.000000 maxuncoupledlength=500
DiffPairsRouting DiffPairsRouting_PCIe_TX0 [InDifferentialPair('PCIE.PCIE_TX0')] p4: maxlimit=5 minlimit=3 mostfreqgap=3 toplayer_maxgap=3.1 toplayer_minwidth=5 toplayer_maxwidth=9.06 toplayer_prefwidth=8 midlayer3_minwidth=3 midlayer3_maxwidth=3.66 midlayer3_prefwidth=3.5 midlayer4_minwidth=3 midlayer4_maxwidth=3.66 midlayer4_prefwidth=3.5 midlayer5_minwidth=3 midlayer5_maxwidth=3.66 midlayer5_prefwidth=3.5 midlayer6_minwidth=3 midlayer6_maxwidth=3.66 midlayer6_prefwidth=3.5 bottomlayer_maxgap=3.1 bottomlayer_minwidth=5 bottomlayer_maxwidth=9.06 bottomlayer_prefwidth=8 impedanceprofiledriven=TRUE impedanceprofileid={3B99ABB2-9DB6-41AF-ADEC-26CBF4FD55D9} impedanceprofilevalue=85.000000 maxuncoupledlength=500
DiffPairsRouting DiffPairsRouting_PCIe_CLK [InDifferentialPair('PCIE.PCIE_CLK')] p5: maxlimit=5 minlimit=3 mostfreqgap=5 toplayer_maxgap=3 toplayer_prefgap=3 toplayer_minwidth=5 toplayer_maxwidth=8 toplayer_prefwidth=5 midlayer3_minwidth=3 midlayer3_maxwidth=3.5 midlayer3_prefwidth=3 midlayer4_minwidth=3 midlayer4_maxwidth=3.5 midlayer4_prefwidth=3 midlayer5_minwidth=3 midlayer5_maxwidth=3.5 midlayer5_prefwidth=3 midlayer6_minwidth=3 midlayer6_maxwidth=3.5 midlayer6_prefwidth=3 bottomlayer_maxgap=3 bottomlayer_prefgap=3 bottomlayer_minwidth=5 bottomlayer_maxwidth=8 bottomlayer_prefwidth=5 impedanceprofiledriven=TRUE impedanceprofileid={C3FD04F3-F1EA-42A3-8B87-5CBABFB4C5AB} impedanceprofilevalue=100.000000 maxuncoupledlength=500
DiffPairsRouting [All] p6: maxlimit=5 minlimit=3 mostfreqgap=5 toplayer_maxgap=3 toplayer_prefgap=3 toplayer_minwidth=5 toplayer_maxwidth=5 toplayer_prefwidth=5 midlayer3_mingap=5 midlayer3_minwidth=3 midlayer3_maxwidth=3 midlayer3_prefwidth=3 midlayer4_mingap=5 midlayer4_minwidth=3 midlayer4_maxwidth=3 midlayer4_prefwidth=3 midlayer5_mingap=5 midlayer5_minwidth=3 midlayer5_maxwidth=3 midlayer5_prefwidth=3 midlayer6_mingap=5 midlayer6_minwidth=3 midlayer6_maxwidth=3 midlayer6_prefwidth=3 bottomlayer_maxgap=3 bottomlayer_prefgap=3 bottomlayer_minwidth=5 bottomlayer_maxwidth=5 bottomlayer_prefwidth=5 maxuncoupledlength=5
FabricationTestPointUsage TestPointUsage [All] p1: valid=0 allowmultiple=FALSE
FabricationTestpoint Testpoint [All] p1: side=3 testpointundercomponent=TRUE minsize=40 maxsize=100 preferedsize=60 minholesize=20 maxholesize=40 preferedholesize=32 testpointgrid=1 allowsidetop=TRUE allowsidebottom=TRUE usegrid=TRUE gridtolerance=0.01
Height "PCI Express, Page 84, \"Component Height Constraints\" for solder side" [OnBottomLayer] p1: minheight=0 maxheight=105.12 prefheight=105.12
Height "PCI Express, Page 84, \"Component Height Constraints\" for component side" [OnTopLayer] p2: minheight=0 maxheight=569.68 prefheight=569.68
HoleSize [All] p1: absolutevalues=TRUE maxlimit=200 minlimit=6 maxpercent=80.000 minpercent=20.000
HoleToHoleClearance [All] p1: gap=8 allowstackedmicrovias=TRUE
MatchedLengths MatchedLengths_RX [InDifferentialPair('PCIE.PCIE_RX0')] p1: tolerance=5 checknetsindiffpair=TRUE checkdiffpairvsdiffpair=FALSE checkxsignals=FALSE checkothers=FALSE
MatchedLengths MatchedLengths_TX [InDifferentialPair('PCIE.PCIE_TX0')] p2: tolerance=5 checknetsindiffpair=TRUE checkdiffpairvsdiffpair=FALSE checkxsignals=FALSE checkothers=FALSE
MatchedLengths MatchedLengths_CLK [InDifferentialPair('PCIE.PCIE_CLK')] p3: tolerance=1 checknetsindiffpair=TRUE checkdiffpairvsdiffpair=FALSE checkxsignals=FALSE checkothers=FALSE
MinimumSolderMaskSliver [All] p1: minsoldermaskwidth=4
PlaneClearance [All] p1: clearance=0
PlaneConnect [All] p1: planeconnectstyle=Direct reliefexpansion=20 reliefentries=4 reliefconductorwidth=10 reliefairgap=10
PolygonConnect PolygonDirectConnect [All vs IsPolygon] p1: connectstyle=Direct reliefconductorwidth=10 reliefentries=4 polygonreliefangle="90 Angle" airgapwidth=10
PolygonConnect [All] p2: connectstyle=Relief reliefconductorwidth=10 reliefentries=4 polygonreliefangle="90 Angle" airgapwidth=10
RoomDefinition Designator [InComponentClass('Designator')] p1: confinementstyle=ConfineIn formatcopy=TRUE lockcomponents=FALSE outline -7165.35,-6259.84 -5165.35,-6259.84 -5165.35,-5259.84 -7165.35,-5259.84
RoomDefinition ChassisTimingInterfacePCIE [InComponentClass('ChassisTimingInterfacePCIE')] p2: confinementstyle=ConfineIn formatcopy=TRUE lockcomponents=FALSE outline -7165.35,-6259.84 -5165.35,-6259.84 -5165.35,-5259.84 -7165.35,-5259.84
RoomDefinition FPGA [InComponentClass('FPGA')] p3: confinementstyle=ConfineIn formatcopy=TRUE lockcomponents=FALSE outline 452.76,452.76 -452.76,452.76 -452.76,-452.76 452.76,-452.76
RoutingVias RoutingVias_BGA [WithinRoom('FPGA')] p1: holewidth=10 width=19 viastyle="Through Hole" minholewidth=10 minwidth=19 maxholewidth=10 maxwidth=19
RoutingVias [All] p2: holewidth=10 width=20 viastyle="Through Hole" minholewidth=6 minwidth=12 maxholewidth=28 maxwidth=50
SilkToSolderMaskClearance SilkscreenOverComponentPads [IsPad] p1: minsilkscreentomaskgap=10 clearancetoexposedcopper=TRUE
SolderMaskExpansion [All] p1: expansion=0 istentingtop=FALSE
Width [All] p1: maxlimit=200 minlimit=3 preferedwidth=10
20 further rules are at their usual default settings.

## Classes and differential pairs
component class Designator: C25 C129 C150 C163 C166 C168 C169 C173 C174 C175 C176 C178 C180 C181 C182 C189 C192 C193 C194 C195 C196 C197 C198 C199 D2 FL1 L1 L8 R136 R138 R139 R141 R143 R144 R146 R147 R148 R149 R150 R151 R152 R153 R154 U36 U37 U38
component class ChassisTimingInterfacePCIE: P3
net class XMUX[3..0]: SQSPI.XMUX0 SQSPI.XMUX1 SQSPI.XMUX2 SQSPI.XMUX3
net class SW[10..1]: CONFIG.SW1 CONFIG.SW2 CONFIG.SW3 CONFIG.SW4 CONFIG.SW5 CONFIG.SW6 CONFIG.SW7 CONFIG.SW8 CONFIG.SW9 CONFIG.SW10
polygon class "No Thermals": SW_PWR_2
component class FPGA: R145 U1_B U16
net class JTAG[1..5]: JTAG1 JTAG2 JTAG3 JTAG4 JTAG5
differential pair XADC.XADC_V: +XADC.XADC_V_P -XADC.XADC_V_N
differential pair XADC.XADC_REF: +XADC.XADC_REF_P -XADC.XADC_REF_N
differential pair S33_48.S48: +S33_48.S48_P -S33_48.S48_N
differential pair S33_48.S47: +S33_48.S47_P -S33_48.S47_N
differential pair S33_48.S46: +S33_48.S46_P -S33_48.S46_N
differential pair S33_48.S45: +S33_48.S45_P -S33_48.S45_N
differential pair S33_48.S44: +S33_48.S44_P -S33_48.S44_N
differential pair S33_48.S43: +S33_48.S43_P -S33_48.S43_N
differential pair S33_48.S42: +S33_48.S42_P -S33_48.S42_N
differential pair S33_48.S41: +S33_48.S41_P -S33_48.S41_N
differential pair S33_48.S40: +S33_48.S40_P -S33_48.S40_N
differential pair S33_48.S39: +S33_48.S39_P -S33_48.S39_N
differential pair S33_48.S38: +S33_48.S38_P -S33_48.S38_N
differential pair S33_48.S37: +S33_48.S37_P -S33_48.S37_N
differential pair S33_48.S36: +S33_48.S36_P -S33_48.S36_N
differential pair S33_48.S35: +S33_48.S35_P -S33_48.S35_N
differential pair S33_48.S34: +S33_48.S34_P -S33_48.S34_N
differential pair S33_48.S33: +S33_48.S33_P -S33_48.S33_N
differential pair XOCTR: +XOCTR_P -XOCTR_N
differential pair EXT_SYNC.EXTSYNC: +EXT_SYNC.EXTSYNC_P -EXT_SYNC.EXTSYNC_N
differential pair XOCTRL: +XOCTRL_P -XOCTRL_N
differential pair DUOTONE: +DUOTONE_P -DUOTONE_N
differential pair X1: +X1_P -X1_N
differential pair REFCLK: +REFCLK_P -REFCLK_N
differential pair BACKPLANE.SCLK: +BACKPLANE.SCLK_P -BACKPLANE.SCLK_N
differential pair BACKPLANE.CLK5: +BACKPLANE.CLK5_P -BACKPLANE.CLK5_N
differential pair BACKPLANE.X5: +BACKPLANE.X5_P -BACKPLANE.X5_N
differential pair BACKPLANE.X3: +BACKPLANE.X3_P -BACKPLANE.X3_N
differential pair PER0: +PER0_P -PER0_N
differential pair POWER.PWRSYNC: +POWER.PWRSYNC_P -POWER.PWRSYNC_N
differential pair DAC_REF.REFCLK: +DAC_REF.REFCLK_P -DAC_REF.REFCLK_N
differential pair DAC_REF.INVSYNC: +DAC_REF.INVSYNC_P -DAC_REF.INVSYNC_N
differential pair DAC_REF.DSYNC: +DAC_REF.DSYNC_P -DAC_REF.DSYNC_N
differential pair DAC_REF.DSCLK: +DAC_REF.DSCLK_P -DAC_REF.DSCLK_N
differential pair DAC_REF.DOUT1: +DAC_REF.DOUT1_P -DAC_REF.DOUT1_N
differential pair DAC_REF.DOUT0: +DAC_REF.DOUT0_P -DAC_REF.DOUT0_N
differential pair CLOCK.SYNC: +CLOCK.SYNC_P -CLOCK.SYNC_N
differential pair CLOCK.OSCCLK: +CLOCK.OSCCLK_P -CLOCK.OSCCLK_N
differential pair CLOCK.CNTROUT: +CLOCK.CNTROUT_P -CLOCK.CNTROUT_N
differential pair CLOCK.AIN: +CLOCK.AIN_P -CLOCK.AIN_N
differential pair CLOCK.ACNV: +CLOCK.ACNV_P -CLOCK.ACNV_N
differential pair CLOCK.ACLK: +CLOCK.ACLK_P -CLOCK.ACLK_N
differential pair SFPIN.SYNCOUT: +SFPIN.SYNCOUT_P -SFPIN.SYNCOUT_N
differential pair SFPIN.SYNCIN: +SFPIN.SYNCIN_P -SFPIN.SYNCIN_N
differential pair PCIE.PCIE_TX0: +PCIE.PCIE_TX0_P -PCIE.PCIE_TX0_N
differential pair PCIE.PCIE_RX0: +PCIE.PCIE_RX0_P -PCIE.PCIE_RX0_N
differential pair PCIE.PCIE_CLK: +PCIE.PCIE_CLK_P -PCIE.PCIE_CLK_N
differential pair BACKPLANE.X1: +BACKPLANE.X1_P -BACKPLANE.X1_N
differential pair BACKPLANE.DOUT: +BACKPLANE.DOUT_P -BACKPLANE.DOUT_N
differential pair BACKPLANE.DIN: +BACKPLANE.DIN_P -BACKPLANE.DIN_N
differential pair BACKPLANE.CS: +BACKPLANE.CS_P -BACKPLANE.CS_N
differential pair BACKPLANE.CLK9: +BACKPLANE.CLK9_P -BACKPLANE.CLK9_N
differential pair BACKPLANE.CLK8: +BACKPLANE.CLK8_P -BACKPLANE.CLK8_N
differential pair BACKPLANE.CLK7: +BACKPLANE.CLK7_P -BACKPLANE.CLK7_N
differential pair BACKPLANE.CLK6: +BACKPLANE.CLK6_P -BACKPLANE.CLK6_N
differential pair BACKPLANE.CLK4: +BACKPLANE.CLK4_P -BACKPLANE.CLK4_N
differential pair BACKPLANE.CLK3: +BACKPLANE.CLK3_P -BACKPLANE.CLK3_N
differential pair BACKPLANE.CLK2: +BACKPLANE.CLK2_P -BACKPLANE.CLK2_N
differential pair BACKPLANE.CLK1: +BACKPLANE.CLK1_P -BACKPLANE.CLK1_N
differential pair BACKPLANE.CLK0: +BACKPLANE.CLK0_P -BACKPLANE.CLK0_N
differential pair T1_11.T11: +T1_11.T11_P -T1_11.T11_N
differential pair T1_11.T10: +T1_11.T10_P -T1_11.T10_N
differential pair T1_11.T9: +T1_11.T9_P -T1_11.T9_N
differential pair T1_11.T8: +T1_11.T8_P -T1_11.T8_N
differential pair T1_11.T7: +T1_11.T7_P -T1_11.T7_N
differential pair T1_11.T6: +T1_11.T6_P -T1_11.T6_N
differential pair T1_11.T5: +T1_11.T5_P -T1_11.T5_N
differential pair T1_11.T4: +T1_11.T4_P -T1_11.T4_N
differential pair T1_11.T3: +T1_11.T3_P -T1_11.T3_N
differential pair T1_11.T2: +T1_11.T2_P -T1_11.T2_N
differential pair T1_11.T1: +T1_11.T1_P -T1_11.T1_N
differential pair S49_64.S64: +S49_64.S64_P -S49_64.S64_N
differential pair S49_64.S63: +S49_64.S63_P -S49_64.S63_N
differential pair S49_64.S62: +S49_64.S62_P -S49_64.S62_N
differential pair S49_64.S61: +S49_64.S61_P -S49_64.S61_N
differential pair S49_64.S60: +S49_64.S60_P -S49_64.S60_N
differential pair S49_64.S59: +S49_64.S59_P -S49_64.S59_N
differential pair S49_64.S58: +S49_64.S58_P -S49_64.S58_N
differential pair S49_64.S57: +S49_64.S57_P -S49_64.S57_N
differential pair S49_64.S56: +S49_64.S56_P -S49_64.S56_N
differential pair S49_64.S55: +S49_64.S55_P -S49_64.S55_N
differential pair S49_64.S54: +S49_64.S54_P -S49_64.S54_N
differential pair S49_64.S53: +S49_64.S53_P -S49_64.S53_N
differential pair S49_64.S52: +S49_64.S52_P -S49_64.S52_N
differential pair S49_64.S51: +S49_64.S51_P -S49_64.S51_N
differential pair S49_64.S50: +S49_64.S50_P -S49_64.S50_N
differential pair S49_64.S49: +S49_64.S49_P -S49_64.S49_N
differential pair S17_32.S32: +S17_32.S32_P -S17_32.S32_N
differential pair S17_32.S31: +S17_32.S31_P -S17_32.S31_N
differential pair S17_32.S30: +S17_32.S30_P -S17_32.S30_N
differential pair S17_32.S29: +S17_32.S29_P -S17_32.S29_N
differential pair S17_32.S28: +S17_32.S28_P -S17_32.S28_N
differential pair S17_32.S27: +S17_32.S27_P -S17_32.S27_N
differential pair S17_32.S26: +S17_32.S26_P -S17_32.S26_N
differential pair S17_32.S25: +S17_32.S25_P -S17_32.S25_N
differential pair S17_32.S24: +S17_32.S24_P -S17_32.S24_N
differential pair S17_32.S23: +S17_32.S23_P -S17_32.S23_N
differential pair S17_32.S22: +S17_32.S22_P -S17_32.S22_N
differential pair S17_32.S21: +S17_32.S21_P -S17_32.S21_N
differential pair S17_32.S20: +S17_32.S20_P -S17_32.S20_N
differential pair S17_32.S19: +S17_32.S19_P -S17_32.S19_N
differential pair S17_32.S18: +S17_32.S18_P -S17_32.S18_N
differential pair S17_32.S17: +S17_32.S17_P -S17_32.S17_N
differential pair S1_16.S16: +S1_16.S16_P -S1_16.S16_N
differential pair S1_16.S15: +S1_16.S15_P -S1_16.S15_N
differential pair S1_16.S14: +S1_16.S14_P -S1_16.S14_N
differential pair S1_16.S13: +S1_16.S13_P -S1_16.S13_N
differential pair S1_16.S12: +S1_16.S12_P -S1_16.S12_N
differential pair S1_16.S11: +S1_16.S11_P -S1_16.S11_N
differential pair S1_16.S10: +S1_16.S10_P -S1_16.S10_N
differential pair S1_16.S9: +S1_16.S9_P -S1_16.S9_N
differential pair S1_16.S8: +S1_16.S8_P -S1_16.S8_N
differential pair S1_16.S7: +S1_16.S7_P -S1_16.S7_N
differential pair S1_16.S6: +S1_16.S6_P -S1_16.S6_N
differential pair S1_16.S5: +S1_16.S5_P -S1_16.S5_N
differential pair S1_16.S4: +S1_16.S4_P -S1_16.S4_N
differential pair S1_16.S3: +S1_16.S3_P -S1_16.S3_N
differential pair S1_16.S2: +S1_16.S2_P -S1_16.S2_N
differential pair S1_16.S1: +S1_16.S1_P -S1_16.S1_N

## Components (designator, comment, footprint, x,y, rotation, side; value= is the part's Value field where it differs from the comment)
C1 "33nF" CC1005-0402 -2401.57,-1181.1 r90 top
C2 "1.0uF" CC1608-0603 -2303.15,-1594.49 r0 top
C3 "33nF" CC1005-0402 -2224.41,-1023.62 r0 top
C4 "1.0uF" CC1608-0603 -2066.93,-1318.9 r180 top
C5 "1.0uF" CC1608-0603 -1984.25,177.17 r180 top
C6 "100nF" CC1005-0402 -1988.19,1003.94 r270 top
C7 "10uF" CC2013-0805 -1960.63,-1366.14 r90 top
C8 "1nF" CC1005-0402 -1870.08,-1555.12 r270 top
C9 "1.0uF" CC1608-0603 -1814.96,-1437.01 r0 top
C10 "1.0uF" CC1608-0603 -1854.33,-1062.99 r90 top
C11 "33nF" CC1005-0402 -1775.59,-1062.99 r270 top
C12 "100nF" CC1005-0402 -1712.6,1003.94 r270 top
C13 "100nF" CC1005-0402 -1696.85,-1062.99 r90 top
C14 "100nF" CC1005-0402 -1645.67,-1476.38 r90 top
C15 "10uF" CC2013-0805 -1633.86,-1318.9 r270 top
C16 "100nF" CC1005-0402 -1614.17,-1062.99 r90 top
C17 "100nF" CC1005-0402 -1476.38,-1673.23 r0 top
C18 "10uF" CC2013-0805 -1437.01,216.54 r90 top
C19 "1.0uF" CC1608-0603 -1375.98,63.98 r90 top
C20 "47uF" CC3216-1206 -1259.84,-1614.17 r270 top
C21 "47uF" CC3216-1206 -1259.84,-1417.32 r90 top
C22 "1nF" CC1005-0402 -1181.1,-181.1 r0 top
C23 "100nF" CC1005-0402 -1161.42,1003.94 r90 top
C24 "1.0uF" CC1608-0603 -984.25,86.72 r90 top
C25 "47uF" CC3216-1206 -826.77,-311.02 r270 top
C26 "10uF" CC2013-0805 826.77,-1515.75 r270 top
C27 "10uF" CC2013-0805 984.25,-1299.21 r0 top
C28 "100nF" CC1005-0402 1141.72,-1515.75 r90 top
C29 "1.0uF" CC1608-0603 1299.21,-551.18 r0 top
C30 "1.0uF" CC1608-0603 1299.21,-59.06 r180 top
C31 "100nF" CC1005-0402 1394.48,977.36 r180 top
C32 "100nF" CC1005-0402 1394.49,927.36 r180 top
C33 "1.0uF" CC1608-0603 1417.32,-19.68 r90 top
C34 "10uF" CC2013-0805 1574.8,-19.68 r180 top
C35 "10nF" CC1005-0402 1661.42,1956.69 r0 top
C36 "" CA053035 1751.97,1122.05 r0 top locked
C37 "1.0u" CC1005-0402 1734.74,-1163.87 r90 top value=1uF
C38 "10uF" CC2013-0805 1811.02,-393.7 r0 top
C39 "100nF" CC1005-0402 1811.02,-314.96 r0 top
C40 "1.0u" CC1005-0402 1803.15,-1220.47 r0 top value=1uF
C41 "1nF" CC1005-0402 1870.08,472.44 r0 top
C42 "1nF" CC1005-0402 1870.08,393.7 r180 top
C43 "10uF" CC2013-0805 1889.76,-1289.36 r270 top
C44 "10uF" CC2013-0805 1889.76,-1114.16 r90 top
C45 "10uF" CC2013-0805 1889.76,-1437.01 r270 top
C46 "10uF" CC2013-0805 1889.76,-968.5 r90 top
C47 "470n" ECQPZ120060-5.0 2015.75,1122.05 r0 top
C48 "100nF" CC1005-0402 1940.94,-984.25 r270 top
C49 "100nF" CC1005-0402 1944.88,-1419.29 r90 top
C50 "NL" CC2013-0805 2027.56,669.29 r180 top
C51 "1.8nF" CC1005-0402 1980.32,-984.25 r270 top
C52 "1.8nF" CC1005-0402 1984.25,-1515.75 r90 top
C53 "1.0u" CC1005-0402 2066.93,-984.25 r90 top value=1uF
C54 "1.0u" CC1005-0402 2106.3,-984.25 r270 top value=1uF
C55 "100nF" CC1005-0402 2185.04,153.54 r180 top
C56 "NL" CC2013-0805 2185.04,224.41 r180 top
C57 "5.6nF" CC1005-0402 2228.35,-1515.75 r90 top
C58 "2.7nF" CC1005-0402 2236.22,-984.25 r270 top
C59 "10uF" CC2013-0805 2287.4,-1397.64 r270 top
C60 "10uF" CC2013-0805 2291.34,-1000 r90 top
C61 "100nF" CC1005-0402 2279.59,-1263.77 r270 top
C62 "100nF" CC1005-0402 2279.59,-1157.47 r90 top
C63 "100nF" CC1005-0402 2303.15,216.54 r90 top
C64 "100nF" CC1005-0402 2303.15,594.49 r270 top
C65 "10nF" CC1005-0402 2437.01,401.57 r0 top
C66 "100nF" CC1005-0402 2440.94,708.66 r180 top
C67 "1nF" CC1005-0402 2559.06,-255.91 r90 top
C68 "1.0uF" CC1608-0603 2610.24,1122.05 r90 top
C69 "47uF" CC3216-1206 2687.01,-1328.73 r90 top
C70 "47uF" CC3216-1206 2687.01,-1092.51 r90 top
C71 "10nF" CC1005-0402 2795.28,1023.62 r0 top
C72 "68u" TC7343-2917 3031.5,610.24 r180 top
C73 "68u" TC7343-2917 3031.5,808.11 r180 top
C74 "10uF" CC2013-0805 3031.5,-362.2 r90 top
C75 "10uF" CC2013-0805 3366.14,1023.62 r0 bottom
C76 "100nF" CC1005-0402 3208.66,1751.97 r180 bottom
C77 "47uF" CC3216-1206 3031.5,-295.28 r180 bottom
C78 "10uF" CC2013-0805 3031.5,-1200.78 r0 bottom
C79 "10uF" CC2013-0805 3031.5,-1122.05 r0 bottom
C80 "10uF" CC2013-0805 3031.5,-177.17 r0 bottom
C81 "100nF" CC1005-0402 2372.05,-1114.66 r180 bottom
C82 "10uF" CC2013-0805 2401.57,433.07 r270 bottom
C83 "1.0uF" CC1608-0603 2185.04,295.28 r180 bottom
C84 "100nF" CC1005-0402 2086.61,1645.67 r180 bottom
C85 "100nF" CC1005-0402 2086.61,1728.35 r180 bottom
C86 "10uF" CC2013-0805 2086.61,1803.15 r180 bottom
C87 "100nF" CC1005-0402 1838.58,1417.32 r0 bottom
C88 "10uF" CC2013-0805 1838.58,1956.69 r0 bottom
C89 "100nF" CC1005-0402 1811.02,137.8 r0 bottom
C90 "100nF" CC1005-0402 1692.72,1496.06 r0 bottom
C91 "10uF" CC2013-0805 1539.37,-15.75 r0 bottom
C92 "100nF" CC1005-0402 1511.81,1783.46 r90 bottom
C93 "10nF" CC1005-0402 1476.38,314.96 r270 bottom
C94 "100nF" CC1005-0402 1043.31,196.85 r90 bottom
C95 "100nF" CC1005-0402 1043.31,354.33 r270 bottom
C96 "100nF" CC1005-0402 964.57,196.85 r90 bottom
C97 "100nF" CC1005-0402 964.57,354.33 r270 bottom
C98 "100nF" CC1005-0402 885.83,196.85 r90 bottom
C99 "100nF" CC1005-0402 885.83,354.33 r270 bottom
C100 "100nF" CC1005-0402 826.77,-1318.9 r90 bottom
C101 "47uF" CC3216-1206 708.66,59.06 r270 bottom
C102 "47uF" CC3216-1206 688.98,-677.17 r180 bottom
C103 "47uF" CC3216-1206 688.98,-535.43 r180 bottom
C104 "47uF" CC3216-1206 688.98,598.43 r180 bottom
C105 "4.7uF" CC1608-0603 610.24,62.99 r270 bottom
C106 "4.7uF" CC1608-0603 551.18,62.99 r270 bottom
C107 "4.7uF" CC1608-0603 503.94,-685.04 r0 bottom
C108 "4.7uF" CC1608-0603 503.94,-606.3 r0 bottom
C109 "4.7uF" CC1608-0603 503.94,-527.56 r0 bottom
C110 "4.7uF" CC1608-0603 503.94,527.56 r0 bottom
C111 "4.7uF" CC1608-0603 503.94,606.3 r0 bottom
C112 "4.7uF" CC1608-0603 503.94,685.04 r0 bottom
C113 "4.7uF" CC1608-0603 492.13,62.99 r270 bottom
C114 "0.47uF" CAPC0603X33X15NL03T05 452.76,-314.96 r180 bottom
C115 "0.47uF" CAPC0603X33X15NL03T05 413.39,118.11 r0 bottom
C116 "0.47uF" CAPC0603X33X15NL03T05 393.7,354.33 r180 bottom
C117 "4.7uF" CC1608-0603 366.14,-685.04 r0 bottom
C118 "4.7uF" CC1608-0603 366.14,-606.3 r0 bottom
C119 "4.7uF" CC1608-0603 366.14,-527.56 r0 bottom
C120 "4.7uF" CC1608-0603 366.14,527.56 r0 bottom
C121 "4.7uF" CC1608-0603 366.14,606.3 r0 bottom
C122 "4.7uF" CC1608-0603 366.14,685.04 r0 bottom
C123 "0.47uF" CAPC0603X33X15NL03T05 374.02,-78.74 r180 bottom
C124 "0.47uF" CAPC0603X33X15NL03T05 374.02,196.85 r180 bottom
C125 "0.47uF" CAPC0603X33X15NL03T05 334.65,78.74 r180 bottom
C126 "0.47uF" CAPC0603X33X15NL03T05 295.28,-374.02 r45 bottom
C127 "0.47uF" CAPC0603X33X15NL03T05 295.28,196.85 r180 bottom
C128 "0.47uF" CAPC0603X33X15NL03T05 216.54,118.11 r180 bottom
C129 "47uF" CC3216-1206 157.48,-531.5 r180 bottom
C130 "1.0uF" CC1608-0603 157.48,0 r180 bottom
C131 "0.47uF" CAPC0603X33X15NL03T05 196.85,-98.43 r270 bottom
C132 "0.47uF" CAPC0603X33X15NL03T05 196.85,216.54 r270 bottom
C133 "0.47uF" CAPC0603X33X15NL03T05 177.17,-196.85 r0 bottom
C134 "0.47uF" CAPC0603X33X15NL03T05 177.17,39.37 r0 bottom
C135 "0.47uF" CAPC0603X33X15NL03T05 177.17,-157.48 r180 bottom
C136 "0.47uF" CAPC0603X33X15NL03T05 177.17,157.48 r180 bottom
C137 "0.47uF" CAPC0603X33X15NL03T05 157.48,-59.06 r90 bottom
C138 "0.47uF" CAPC0603X33X15NL03T05 137.8,-118.11 r180 bottom
C139 "0.47uF" CAPC0603X33X15NL03T05 118.11,-177.17 r270 bottom
C140 "0.47uF" CAPC0603X33X15NL03T05 98.43,-78.74 r180 bottom
C141 "0.47uF" CAPC0603X33X15NL03T05 98.43,-39.37 r180 bottom
C142 "0.47uF" CAPC0603X33X15NL03T05 78.74,413.39 r270 bottom
C143 "0.47uF" CAPC0603X33X15NL03T05 59.06,-433.07 r0 bottom
C144 "0.47uF" CAPC0603X33X15NL03T05 59.06,-157.48 r0 bottom
C145 "0.47uF" CAPC0603X33X15NL03T05 59.06,-196.85 r180 bottom
C146 "0.47uF" CAPC0603X33X15NL03T05 19.68,39.37 r0 bottom
C147 "1.0uF" CC1608-0603 0,-354.33 r90 bottom
C148 "0.47uF" CAPC0603X33X15NL03T05 -19.69,-98.43 r315 bottom
C149 "0.47uF" CAPC0603X33X15NL03T05 -19.69,236.15 r180 bottom
C150 "1.0uF" CC1608-0603 -59.06,-570.87 r0 bottom
C151 "0.47uF" CAPC0603X33X15NL03T05 -59.06,59.06 r225 bottom
C152 "0.47uF" CAPC0603X33X15NL03T05 -59.06,374.02 r225 bottom
C153 "0.47uF" CAPC0603X33X15NL03T05 -59.06,-196.85 r180 bottom
C154 "0.47uF" CAPC0603X33X15NL03T05 -78.74,-98.43 r90 bottom
C155 "0.47uF" CAPC0603X33X15NL03T05 -118.11,-59.06 r90 bottom
C156 "0.47uF" CAPC0603X33X15NL03T05 -118.11,59.06 r90 bottom
C157 "0.47uF" CAPC0603X33X15NL03T05 -137.8,-157.48 r0 bottom
C158 "0.47uF" CAPC0603X33X15NL03T05 -137.8,-196.85 r180 bottom
C159 "0.47uF" CAPC0603X33X15NL03T05 -137.8,-118.11 r180 bottom
C160 "0.47uF" CAPC0603X33X15NL03T05 -177.17,-236.22 r0 bottom
C161 "0.47uF" CAPC0603X33X15NL03T05 -177.17,39.37 r0 bottom
C162 "0.47uF" CAPC0603X33X15NL03T05 -177.17,-78.74 r180 bottom
C163 "100n" CAPC0603X33X15NL03T05 -196.85,-137.8 r90 bottom
C164 "0.47uF" CAPC0603X33X15NL03T05 -236.22,-413.39 r90 bottom
C165 "0.47uF" CAPC0603X33X15NL03T05 -236.22,452.76 r270 bottom
C166 "100n" CAPC0603X33X15NL03T05 -255.91,-118.11 r0 bottom
C167 "0.47uF" CAPC0603X33X15NL03T05 -255.91,39.37 r0 bottom
C168 "10uF" CC2013-0805 -314.96,-570.87 r0 bottom
C169 "100n" CAPC0603X33X15NL03T05 -295.28,-157.48 r180 bottom
C170 "4.7uF" CC1608-0603 -366.14,527.56 r180 bottom
C171 "4.7uF" CC1608-0603 -366.14,606.3 r180 bottom
C172 "4.7uF" CC1608-0603 -366.14,685.04 r180 bottom
C173 "100n" CAPC0603X33X15NL03T05 -334.65,-314.96 r0 bottom
C174 "100n" CAPC0603X33X15NL03T05 -334.65,-236.22 r0 bottom
C175 "100n" CAPC0603X33X15NL03T05 -334.65,-78.74 r180 bottom
C176 "4.7uF" CC1608-0603 -354.33,-688.98 r270 bottom
C177 "0.47uF" CAPC0603X33X15NL03T05 -354.33,-452.76 r90 bottom
C178 "100n" CAPC0603X33X15NL03T05 -354.33,-137.8 r270 bottom
C179 "0.47uF" CAPC0603X33X15NL03T05 -374.02,413.39 r315 bottom
C180 "100n" CAPC0603X33X15NL03T05 -413.39,-275.59 r0 bottom
C181 "100n" CAPC0603X33X15NL03T05 -413.39,-196.85 r0 bottom
C182 "100n" CAPC0603X33X15NL03T05 -413.39,-118.11 r0 bottom
C183 "0.47uF" CAPC0603X33X15NL03T05 -413.39,118.11 r0 bottom
C184 "1.0uF" CC1608-0603 -421.26,1786.61 r270 bottom
C185 "0.47uF" CAPC0603X33X15NL03T05 -452.76,236.22 r0 bottom
C186 "4.7uF" CC1608-0603 -503.94,527.56 r180 bottom
C187 "4.7uF" CC1608-0603 -503.94,606.3 r180 bottom
C188 "4.7uF" CC1608-0603 -503.94,685.04 r180 bottom
C189 "10uF" CC2013-0805 -610.24,-27.56 r180 bottom
C190 "47uF" CC3216-1206 -688.98,551.18 r0 bottom
C191 "47uF" CC3216-1206 -688.98,677.17 r0 bottom
C192 "1.0uF" CC1608-0603 -641.73,-224.41 r270 bottom
C193 "220n" CC1005-0402 -724.41,-1720.47 r90 bottom
C194 "220n" CC1005-0402 -759.84,-1720.47 r90 bottom
C195 "100nF" CC1005-0402 -846.46,-1437.01 r180 bottom
C196 "100nF" CC1005-0402 -846.46,-1397.64 r180 bottom
C197 "4.7uF" CC1608-0603 -885.83,-23.62 r0 bottom
C198 "10nF" CC1005-0402 -842.52,-1720.47 r90 bottom
C199 "10nF" CC1005-0402 -877.95,-1720.47 r90 bottom
C200 "100nF" CC1005-0402 -1082.68,1129.92 r180 bottom
C201 "1.0uF" CC1608-0603 -1082.68,19.69 r270 bottom
C202 "1.0uF" CC1608-0603 -1279.53,19.69 r270 bottom
C203 "1.0uF" CC1608-0603 -1374.02,-1389.76 r270 bottom
C204 "10uF" CC2013-0805 -1393.7,11.81 r270 bottom
C205 "10nF" CC1005-0402 -1409.45,-1279.53 r180 bottom
C206 "10uF" CC2013-0805 -1574.8,-1062.99 r90 bottom
C207 "1.0uF" CC1608-0603 -1574.8,-161.42 r270 bottom
C208 "47uF" CC3216-1206 -1594.49,-1389.76 r270 bottom
C209 "10uF" CC2013-0805 -1700.79,-1527.56 r90 bottom
C210 "1.0uF" CC1608-0603 -1771.65,-401.57 r0 bottom
C211 "1.0uF" CC1608-0603 -1811.02,-1161.42 r0 bottom
C212 "1.0uF" CC1608-0603 -1929.13,-401.57 r0 bottom
C213 "47uF" CC3216-1206 -2027.56,-1003.94 r180 bottom
C214 "1.0uF" CC1608-0603 -2086.61,-401.57 r0 bottom
C215 "100nF" CC1005-0402 -2145.67,-1161.42 r180 bottom
C216 "1.0uF" CC1608-0603 -2244.09,-401.57 r0 bottom
C217 "100nF" CC1005-0402 -2303.15,-775.59 r180 bottom
C218 "10nF" CC1005-0402 -2303.15,-1161.42 r0 bottom
D1 "LSM115JE3/TR13" MCSM-DO-214BA-2_L 2952.76,-629.92 r90 top
D2 "LSM115JE3/TR13" MCSM-DO-214BA-2_L -291.34,-1279.53 r0 bottom
DS1 "LED" LED-0805 -1299.21,-413.39 r90 top
DS2 "604-APA2107LZGCK" KING-LED2107-13-RED-2_V 3740.16,1559.06 r90 bottom
DS3 "604-APA2106SURCK" KING-LED2107-13-RED-2_V 3740.16,1830.71 r90 bottom
FL1 "BNX016-01" MURA-BNX016-01_V -433.07,-1515.75 r0 top locked
FL2 "BNX016-01" MURA-BNX016-01_V 39.37,-1515.75 r0 top locked
FL3 "BNX016-01" MURA-BNX016-01_V 511.81,-1515.75 r180 top
FL4 "BNX016-01" MURA-BNX016-01_V 3031.5,-964.57 r90 top
FL5 "BNX016-01" MURA-BNX016-01_V 3031.5,0 r90 top locked
FR1 "BLM31PG121" CC3216-1206 -1181.1,177.17 r180 top
FR2 "BLM31PG121" CC3216-1206 -846.46,86.61 r0 top
FR3 "BLM31PG121" CC3216-1206 2047.24,-354.33 r0 bottom
FR4 "BLM31PG121" CC3216-1206 -1110.24,-161.42 r180 bottom
FR5 "BLM31PG121" CC3216-1206 -1338.58,137.8 r0 bottom
FR6 "BLM31PG121" CC3216-1206 -2177.17,-295.28 r180 bottom
J1 "DB37M" DB37M-RA -2888.98,-260.65 r90 top locked
J2 "AFBR-5710" MSA/SFP2x10 2271.65,1561.81 r180 top locked
J3 "45558-0003" 455580003 3232.53,-1337.35 r270 top
J4 "DB25F" DB25F-RA 3425.2,-118.11 r270 top locked
J5 "SMA" SMA-RA 3602.36,1122.05 r90 top
L1 "100nH" CL2520-1008 -673.23,-354.33 r0 top
L2 "XFL4020-222" FP-XAL40-MFG 1768.58,-1444.33 r270 top value=10uH
L3 "XFL4020-472" FP-XAL40-MFG 1768.58,-979.33 r90 top value=10uH
L4 "XFL4020-332" FP-XAL40-MFG 2503.58,-1444.33 r0 top value=10uH
L5 "XFL4020-222" FP-XAL40-MFG 2503.58,-979.33 r0 top value=10uH
L6 "1uH" CL2520-1008 1968.5,1543.31 r270 bottom
L7 "1uH" CL2520-1008 1968.5,1830.71 r90 bottom
L8 "100nH" CL2520-1008 192.91,-688.98 r0 bottom
LOGO1 "LIGO logo" LIGO-LOGO-SM -3051.18,1901.57 r0 top
P1 "609-5123-ND" 9181089621 -2283.46,1003.94 r90 top
P2 "2mm Header 2x7" 2MM_HDR2X7_RA -1456.69,1712.6 r0 top
P3 "PCIeX1-GF-2D-1000-1K-O36" PCIeX1-GF-2D-1000-1K-O36 -1057.09,-2185.04 r0 top
P4 "QSE40" QSE040 315.75,-1013.39 r0 top locked
P5 "QSE40" QSE040 315.75,1786.61 r0 top locked
Q1 "FDV301N" SO-G3/C2.25 -1181.1,-433.07 r180 top
Q2 "MMBT3906LT1G" ONSC-SOT-23-3-318-08_V 1122.05,-236.22 r90 top
Q3 "MMBT3906LT1G" ONSC-SOT-23-3-318-08_V 1299.21,-236.22 r90 top
Q4 "SI7252DP-T1-GE3" VISH-POWERPAKSO-8_A_V 2440.94,-1210.63 r180 top
Q5 "FDV301N" SO-G3/C2.25 3622.05,1929.13 r90 bottom
Q6 "FDV301N" SO-G3/C2.25 984.25,-1515.75 r0 bottom
R1 "20" CR1005-0402 -2480.32,-1574.8 r180 top
R2 "20" CR1005-0402 -2480.32,-1535.43 r180 top
R3 "4.99K" CR1608-0603 -2381.89,-1023.62 r180 top
R4 "10K" CR1005-0402 -2283.46,-1181.1 r270 top
R5 "220" CR1608-0603 -2244.09,-295.28 r0 top
R6 "220" CR1608-0603 -2086.61,-295.28 r0 top
R7 "4.99K" CR1608-0603 -2066.93,-1023.62 r180 top
R8 "10K" CR1005-0402 -2066.93,-1692.91 r180 top
R9 "10K" CR1005-0402 -2066.93,-1417.32 r180 top
R10 "220" CR1608-0603 -1929.13,-295.28 r180 top
R11 "10K" CR1005-0402 -1854.33,-1259.84 r270 top
R12 "220" CR1608-0603 -1771.65,-295.28 r180 top
R13 "10K" CR1005-0402 -1736.22,-1259.84 r180 top
R14 "100K" CR1005-0402 -1736.22,-1181.1 r180 top
R15 "4.99K" CR1608-0603 -1755.91,-1555.12 r90 top
R16 "6.42K" CR1608-0603 -1633.86,-295.28 r90 top
R17 "NL" CR1608-0603 -1574.8,-66.93 r180 top
R18 "100" CR1608-0603 -1515.75,-295.28 r270 top
R19 "1.0k" CR1608-0603 -1417.32,-161.42 r90 top value=1.00K
R20 "100" CR1608-0603 -1338.58,1555.12 r270 top
R21 "1.0k" CR1608-0603 -1299.21,-314.96 r180 top
R22 "100" CR1608-0603 -1259.84,1555.12 r270 top
R23 "49.9" CR1608-0603 -1181.1,-255.91 r0 top
R24 "49.9" CR1608-0603 -1181.1,-133.86 r0 top
R25 "4.7k" CR1005-0402 -1181.1,-314.96 r180 top
R26 "100" CR1608-0603 -1181.1,1555.12 r270 top
R27 "100" CR1608-0603 -1102.36,1555.12 r270 top
R28 "NL" CR1005-0402 196.85,511.81 r90 top
R29 "1.0k" CR1608-0603 255.91,511.81 r90 top
R30 "100" CR1608-0603 669.29,1061.93 r270 top
R31 "100" CR1608-0603 748.52,1062.8 r270 top
R32 "1.8k" CR1005-0402 812.99,977.36 r180 top
R33 "1.8k" CR1005-0402 812.99,1277.36 r180 top
R34 "NL" CR1005-0402 812.99,927.36 r0 top
R35 "100" CR1608-0603 826.77,1062.99 r90 top
R36 "NL" CR1005-0402 1027.56,866.14 r180 top
R37 "1.0k" CR1608-0603 1035.43,-1692.91 r0 top
R38 "4.7k" CR1005-0402 1043.02,669.29 r90 top
R39 "100" CR1608-0603 1102.36,846.46 r270 top
R40 "1.8k" CR1005-0402 1177.36,866.14 r0 top
R41 "10.0" CR1005-0402 1299.21,19.69 r0 top value=10
R42 "4.7k" CR1005-0402 1394.48,1227.36 r180 top
R43 "1.8k" CR1005-0402 1394.48,1027.36 r0 top
R44 "1.8k" CR1005-0402 1394.48,1277.36 r0 top
R45 "1.0k" CR1608-0603 1476.38,-236.22 r270 top value=1.00K
R46 "1.0k" CR1608-0603 1535.43,-456.69 r0 top value=1.00K
R47 "1.0k" CR1608-0603 1535.43,-370.08 r0 top value=1.00K
R48 "10m" CC3216-1206 1610.24,-850.39 r270 top
R49 "10m" CC3216-1206 1621.55,-1582.18 r270 top
R50 "10K" CR1005-0402 1712.6,275.59 r0 top
R51 "10K" CR1005-0402 1712.6,590.55 r0 top
R52 "1.91k" CR1005-0402 1712.6,-1262.96 r0 top
R53 "392" CR2012-0805 1732.28,1633.86 r180 top
R54 "392" CR2012-0805 1732.28,1555.12 r0 top
R55 "49.9" CR1608-0603 1732.28,1732.28 r0 top
R56 "49.9" CR1608-0603 1732.28,1811.02 r0 top
R57 "22K" CR2012-0805 1732.28,1889.76 r0 top
R58 "4.99k" CR1608-0603 1692.91,-1165.35 r90 top
R59 "10K" CR1005-0402 1870.08,275.59 r0 top
R60 "10K" CR1005-0402 1870.08,590.55 r0 top
R61 "NL" CR1005-0402 1960.63,-1692.91 r180 top
R62 "2.0k" CR1005-0402 1960.63,-1649.61 r0 top
R63 "0" CR1005-0402 1960.63,-1606.3 r0 top
R64 "30K" CR2012-0805 2027.56,590.55 r0 top
R65 "15k" CR1005-0402 1984.25,-1417.32 r90 top
R66 "9.31k" CR1005-0402 2019.68,-984.25 r270 top
R67 "31.6k" CR1005-0402 2055.12,-1488.19 r180 top
R68 "12.7k" CR1005-0402 2055.12,-866.14 r180 top
R69 "10k" CR1005-0402 2055.12,-1437.01 r0 top value=10.2k
R70 "10k" CR1005-0402 2055.12,-905.51 r0 top value=10.2k
R71 "NL" CR1005-0402 2047.24,-1582.68 r90 top
R72 "2.0k" CR1005-0402 2106.3,-1692.91 r0 top
R73 "0" CR1005-0402 2086.61,-1582.68 r270 top
R74 "NL" CR1005-0402 2125.98,-1582.68 r90 top
R75 "40.2k" CR1005-0402 2157.48,-1437.01 r180 top value=40k
R76 "10k" CR1005-0402 2157.48,-905.51 r180 top value=10.2k
R77 "10k" CR1005-0402 2157.48,-1488.19 r0 top
R78 "21.5K" CR1005-0402 2157.48,-866.14 r0 top value=21.5k
R79 "30K" CR2012-0805 2185.04,295.28 r0 top
R80 "37.4k" CR1005-0402 2141.73,-984.25 r90 top value=37k
R81 "NL" CR1005-0402 2165.35,-1582.68 r90 top
R82 "56.2k" CR1005-0402 2192.91,-984.25 r270 top
R83 "2.0k" CR1005-0402 2255.91,-1692.91 r180 top
R84 "0" CR1005-0402 2255.91,-1649.61 r180 top
R85 "0" CR1005-0402 2255.91,-1606.3 r180 top
R86 "7.15k" CR1005-0402 2228.35,-1419.29 r90 top
R87 "1.0K" CR1608-0603 2440.94,476.38 r180 top
R88 "7.15K" CR1005-0402 2440.94,244.09 r0 top
R89 "10k" CR1005-0402 2437.01,322.83 r0 top
R90 "10K" CR1005-0402 2440.94,551.18 r0 top
R91 "10K" CR1005-0402 2440.94,629.92 r0 top
R92 "1.0K" CR1608-0603 2480.32,-255.91 r90 top
R93 "47k" CR1005-0402 2608.27,-1259.83 r270 top
R94 "NL" CR1005-0402 2608.27,-1161.41 r270 top
R95 "1.0K" CR1608-0603 2637.8,-255.91 r90 top
R96 "10m" CC3216-1206 2691.93,-1582.18 r270 top
R97 "10m" CC3216-1206 2691.93,-843.99 r90 top
R98 "22K" CR2012-0805 2795.28,1220.47 r180 top
R99 "10m" CC3216-1206 2901.57,-362.2 r90 top
R100 "49.9" CR1608-0603 2972.44,1122.05 r270 top
R101 "261" CR2012-0805 3287.4,1122.05 r270 top
R102 "20" CR1005-0402 3385.83,1122.05 r90 top
R103 "100" CR1608-0603 3622.05,1476.38 r180 bottom
R104 "100" CR1608-0603 3622.05,1751.97 r180 bottom
R105 "261" CR2012-0805 3464.57,1122.05 r0 bottom
R106 "NL" CR2012-0805 3366.14,1220.47 r180 bottom
R107 "10.0" CR1005-0402 3208.66,1673.23 r180 bottom value=10
R108 "10.0" CR1005-0402 2385.83,-1023.62 r90 bottom value=10
R109 "4.7k" CR1005-0402 2322.83,-984.25 r90 bottom value=4.65k
R110 "4.7k" CR1005-0402 2263.78,1593.31 r180 bottom
R111 "4.7k" CR1005-0402 2263.78,1653.54 r180 bottom
R112 "4.7k" CR1005-0402 2263.78,1692.91 r180 bottom
R113 "4.7k" CR1005-0402 2263.78,1750.79 r180 bottom
R114 "4.7k" CR1005-0402 2263.78,1813.78 r180 bottom
R115 "7.15k" CR1005-0402 2279.53,-984.25 r270 bottom
R116 "0" CR1005-0402 2236.22,-984.25 r270 bottom
R117 "2.0k" CR1005-0402 2224.41,-1627.95 r90 bottom
R118 "NL" CR1005-0402 2192.91,-984.25 r90 bottom
R119 "0" CR1005-0402 2141.73,-984.25 r270 bottom
R120 "NL" CR1005-0402 2106.3,-984.25 r90 bottom
R121 "100k" CR1005-0402 2066.93,-984.25 r270 bottom
R122 "402k" CR1005-0402 2019.68,-984.25 r90 bottom
R123 "10k" CR1005-0402 1968.5,-1387.8 r0 bottom
R124 "9.53k" CR1005-0402 1968.5,-1328.74 r180 bottom
R125 "301k" CR1005-0402 1980.32,-984.25 r270 bottom
R126 "7.15k" CR1005-0402 1940.94,-984.25 r90 bottom
R127 "7.15k" CR1005-0402 1889.76,-986.22 r90 bottom
R128 "7.15K" CR1005-0402 1385.83,74.78 r270 bottom
R129 "1.0K" CR1608-0603 1385.83,208.66 r90 bottom
R130 "100K" CR1005-0402 1342.65,-27.56 r180 bottom
R131 "4.7k" CR1005-0402 590.55,-216.54 r0 bottom
R132 "4.7k" CR1005-0402 590.55,-177.17 r0 bottom
R133 "4.7k" CR1005-0402 590.55,-137.8 r0 bottom
R134 "4.7k" CR1005-0402 590.55,-98.43 r0 bottom
R135 "4.7k" CR1005-0402 590.55,-59.06 r0 bottom
R136 "49.9K" CR1005-0402 78.74,-688.98 r90 bottom
R137 "1.0k" CR1608-0603 -39.37,-1279.53 r90 bottom value=1.00K
R138 "300" CR1005-0402 -59.06,-787.4 r0 bottom
R139 "49.9K" CR1005-0402 -117.18,-826.77 r180 bottom
R140 "1.0k" CR1608-0603 -118.11,-1279.53 r90 bottom value=1.00K
R141 "100K" CR1005-0402 -177.17,-787.4 r180 bottom
R142 "100K" CR1005-0402 -196.85,-1614.17 r180 bottom
R143 "10m" CC3216-1206 -196.85,-1456.69 r270 bottom
R144 "10K" CR1005-0402 -295.28,-688.98 r270 bottom
R145 "100" CR1608-0603 -614.17,-98.43 r180 bottom
R146 "15" CR1005-0402 -669.29,-1720.47 r90 bottom
R147 "NL" CR1005-0402 -677.17,-1417.32 r270 bottom
R148 "NL" CR1005-0402 -748.03,-1515.75 r180 bottom
R149 "49.9K" CR1005-0402 -767.72,-374.02 r0 bottom
R150 "12.1K" CR1005-0402 -767.72,-11.81 r180 bottom
R151 "300" CR1005-0402 -866.14,-236.22 r270 bottom
R152 "49.9K" CR1005-0402 -866.14,-106.3 r90 bottom
R153 "133K" CR1005-0402 -905.51,-106.3 r270 bottom
R154 "0" CR1005-0402 -976.87,-1719.98 r180 bottom
R155 "100" CR1608-0603 -1496.06,905.51 r270 bottom
R156 "100" CR1608-0603 -1496.06,1102.36 r90 bottom
R157 "4.7k" CR1005-0402 -1574.8,1791.34 r0 bottom
R158 "100" CR1608-0603 -1574.8,905.51 r270 bottom
R159 "100" CR1608-0603 -1574.8,1102.36 r90 bottom
R160 "100K" CR1005-0402 -1653.54,-767.72 r180 bottom
R161 "100" CR1608-0603 -1653.54,905.51 r270 bottom
R162 "100" CR1608-0603 -1653.54,1102.36 r90 bottom
R163 "7.15K" CR1005-0402 -1712.6,19.69 r90 bottom
R164 "100" CR1608-0603 -1716.54,-527.56 r270 bottom
R165 "100" CR1608-0603 -1771.65,905.51 r270 bottom
R166 "100" CR1608-0603 -1771.65,1102.36 r90 bottom
R167 "10K" CR1005-0402 -1771.65,19.69 r90 bottom
R168 "6.42K" CR1608-0603 -1771.65,-527.56 r270 bottom
R169 "40.2K" CR1608-0603 -1811.02,-767.72 r180 bottom
R170 "3.01K" CR1608-0603 -1822.83,-527.56 r270 bottom
R171 "10K" CR1005-0402 -1830.71,-137.8 r90 bottom
R172 "10K" CR1005-0402 -1830.71,19.69 r90 bottom
R173 "100" CR1608-0603 -1850.39,905.51 r270 bottom
R174 "100" CR1608-0603 -1850.39,1102.36 r90 bottom
R175 "100" CR1608-0603 -1874.02,-527.56 r270 bottom
R176 "4.99K" CR1608-0603 -1889.76,-137.8 r90 bottom
R177 "10K" CR1005-0402 -1889.76,19.69 r90 bottom
R178 "100" CR1608-0603 -1929.13,905.51 r270 bottom
R179 "100" CR1608-0603 -1929.13,1102.36 r90 bottom
R180 "6.42K" CR1608-0603 -1929.13,-527.56 r270 bottom
R181 "49.9K" CR1005-0402 -1968.5,-767.72 r180 bottom
R182 "4.99K" CR1608-0603 -1948.82,-137.8 r90 bottom
R183 "10K" CR1005-0402 -1948.82,19.69 r90 bottom
R184 "20" CR1005-0402 -1988.19,-1177.17 r0 bottom
R185 "10K" CR1005-0402 -1988.19,-1133.86 r0 bottom
R186 "1.0K" CR1608-0603 -1980.32,-527.56 r270 bottom
R187 "30.1K" CR1608-0603 -2007.87,-137.8 r90 bottom
R188 "10K" CR1005-0402 -2007.87,19.69 r90 bottom
R189 "100" CR1608-0603 -2031.5,-527.56 r270 bottom
R190 "49.9K" CR1005-0402 -2066.93,-137.8 r90 bottom
R191 "10K" CR1005-0402 -2066.93,19.69 r90 bottom
R192 "6.42K" CR1608-0603 -2086.61,-527.56 r270 bottom
R193 "49.9K" CR1005-0402 -2125.98,-767.72 r180 bottom
R194 "7.15K" CR1005-0402 -2125.98,19.69 r90 bottom
R195 "1.0K" CR1608-0603 -2137.8,-527.56 r270 bottom
R196 "10K" CR1005-0402 -2185.04,19.69 r90 bottom
R197 "100" CR1608-0603 -2188.98,-527.56 r270 bottom
R198 "6.42K" CR1608-0603 -2244.09,-527.56 r270 bottom
R199 "10K" CR1005-0402 -2244.09,19.69 r90 bottom
R200 "1.0K" CR1608-0603 -2295.28,-527.56 r270 bottom
R201 "10K" CR1005-0402 -2303.15,19.69 r90 bottom
R202 "NL" CR1005-0402 -2633.86,-968.5 r225 bottom
R203 "NL" CR1005-0402 -2661.42,-940.94 r225 bottom
S1 "SW DIP-8" DIP_SW_8WAY_SMD_SIDE -2070.87,1783.46 r180 top locked
S2 "B3SN-3112P" SW_SMD_6MM -1732.28,1791.34 r180 bottom
T1 "1:1" AT224-3 3070.87,1172.05 r0 top
TP1 "Testpoint" TP1-RED#1 -2106.3,-846.46 r90 top
TP2 "Testpoint" TP1-WHT -1948.82,-846.46 r270 top
TP3 "Testpoint" TP1-RED#1 -1673.23,-1669.29 r270 top
TP4 "Testpoint" TP1-BLK#1 -1456.69,1555.12 r270 top
TP5 "Testpoint" TP1-WHT -1141.73,-1673.23 r270 top
TP6 "Testpoint" TP1-BLK#1 -1141.73,-1515.75 r270 top
TP7 "Testpoint" TP1-RED#1 -1141.73,-1358.27 r90 top
TP8 "Testpoint" TP1-BLK#1 1299.21,1437.01 r270 top
TP9 "Testpoint" TP1-RED#1 1614.17,-1210.63 r90 top
TP10 "Testpoint" TP1-RED#1 1614.17,-1003.94 r90 top
TP11 "Testpoint" TP1-YLW#1 1732.28,-775.59 r0 top
TP12 "Testpoint" TP1-RED#1 1771.65,-1663.39 r90 top
TP13 "Testpoint" TP1-BLK#1 1909.45,-777.56 r90 top
TP14 "Testpoint" TP1-BLK#1 2007.87,-688.98 r90 top
TP15 "Testpoint" TP1-RED#1 2106.3,-777.56 r90 top
TP16 "Testpoint" TP1-YLW#2 2185.04,669.29 r180 top
TP17 "Testpoint" TP1-YLW#2 2185.04,826.77 r180 top
TP18 "Testpoint" TP1-BLK#1 2204.72,-688.98 r90 top
TP19 "Testpoint" TP1-RED#1 2303.15,-777.56 r90 top
TP20 "Testpoint" TP1-BLK#2 2401.57,-1675.69 r90 top
TP21 "Testpoint" TP1-RED#1 2500,-777.56 r0 top
TP22 "Testpoint" TP1-RED#2 2559.06,-1675.2 r90 top
TP23 "Testpoint" TP1-BLK#1 2795.28,885.83 r270 top
TP24 "Testpoint" TP1-BLK#1 2921.26,-1603.72 r0 top
TP25 "Testpoint" TP1-RED#1 2921.26,-1406.87 r0 top
TP26 "Testpoint" TP1-YLW#2 3129.92,964.57 r90 top
U1 "INA333AIDGKR" DGK0008A_N -2244.09,-492.13 r90 top
U2 "ADG706BRU" ADI-RU-28_M -2007.87,-39.37 r270 top locked
U3 "OP184ES" SO-8_N -2066.93,-1555.12 r180 top
U4 "OP284ES" SO-8_N -2066.93,-1181.1 r180 top locked
U5 "INA333AIDGKR" DGK0008A_N -2086.61,-492.13 r90 top
U6 "INA333AIDGKR" DGK0008A_N -1929.13,-492.13 r90 top
U7 "74LVC04" TSSOP14 -1850.39,1003.94 r0 top locked
U8 "INA333AIDGKR" DGK0008A_N -1771.65,-492.13 r90 top
U9 "INA333AIDGKR" DGK0008A_N -1574.8,-161.42 r0 top
U10 "74LVC04" TSSOP14 -1574.8,1003.94 r0 top locked
U11 "AD5060" SSO-G8/SM8 -1476.38,-1555.12 r270 top
U12 "AD5060" SSO-G8/SM8 -1476.38,-1181.1 r270 top
U13 "74LVC74D" TSSOP14 -1299.21,1003.94 r180 top
U14 "SN65LVDT390" TSSOP16 -1181.1,-708.66 r90 top
U15 "SN74LVC4T245" TSSOP16 -1181.1,0 r270 top
U16 "XC7A35T-2FGG484C" FGG484 0,0 r90 top locked
U17 "SN65LVDT14QPWREP" PW0020A_N 964.57,275.59 r0 top locked
U18 "S25FL128SAGMFI001" FP-002-15547-MFG 1102.36,1102.36 r180 top locked
U19 "LTC1144" SO-G8 984.25,-1515.75 r180 top
U20 "S25FL128SAGNFI003" SPSN-WSON-8_L 1102.36,1122.05 r270 top locked
U21 "OP284ES" SO-8_N 1299.21,-413.39 r180 top
U22 "AD7685" TSSO3x5-G10 1299.21,137.8 r90 top
U23 "74LVC74D" TSSOP14 1299.21,393.7 r180 top
U24 "OP284ES" SO-8_N 1574.8,137.8 r180 top
U25 "SN74LVC1G00" SO-G5/E2.4 1574.8,393.7 r0 top
U26 "ADP5050ACPZ-R7" CP-48-13_L 2106.3,-1200.79 r0 top value=Value
U27 "33.554432MHz" VECTRON_C5310 2358.27,-354.33 r180 top
U28 "OP284ES" SO-8_N 2185.04,433.07 r0 top
U29 "SN65LVDS100D" MSOP8 2795.28,1122.05 r90 top
U30 "SN65LVDT2" SO-G5/E2.4 2381.89,-1210.63 r270 bottom
U31 "ADR425BR" SO-G8 2185.04,433.07 r270 bottom
U32 "SN65LVDS100D" MSOP8 1692.91,1783.46 r270 bottom
U33 "SN65LVDT101D" MSOP8 1692.91,1594.49 r90 bottom
U34 "LT1763" SO-G8 1574.8,137.8 r90 bottom
U35 "SN65LVDT2" SO-G5/E2.4 984.25,-1318.9 r90 bottom
U36 "LT3045" MSOP12_PAD -118.11,-688.98 r180 bottom locked
U37 "LT3045" MSOP12_PAD -767.72,-177.17 r90 bottom locked
U38 "SN74AVC1T45" SC70 -748.03,-1417.32 r0 bottom
U39 "SN65LVDT2" SO-G5/E2.4 -1062.99,1003.94 r0 bottom
U40 "REF3033AIDBZRG4" TI-DBZ3_N -1181.1,19.69 r270 bottom
U41 "LT1964ES5-5" LT-S5-5-TSOT-23_M -1472.44,-1397.64 r270 bottom
U42 "ADR421ARZ" ADI-R-8_M -1732.28,-964.57 r270 bottom
U43 "LT1763" SO-G8 -2303.15,-964.57 r180 bottom
W1 "Net tie" NETTIE1_BOTH -1141.73,-1140.16 r270 top net-tie
W2 "Net tie" NETTIE1_SMDTOP -992.79,67 r0 bottom net-tie
Y1 "DSC1001DI1-025.0000T" FP-CDFN2520-4LD-PL-1-MFG 964.28,669.42 r270 top

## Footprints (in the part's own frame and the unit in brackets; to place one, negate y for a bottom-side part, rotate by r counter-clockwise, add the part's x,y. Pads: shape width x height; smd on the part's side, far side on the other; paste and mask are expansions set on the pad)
2MM_HDR2X7_RA [mm] "Connector; 2mm Header; 7x2 Position, RA"
  rect 1.5x1.5 hole 0.9: 1(0,0)
  round 1.5 hole 0.9: 2(0,2) 3(2,0) 4(2,2) 5(4,0) 6(4,2) 7(6,0) 8(6,2) 9(8,0) 10(8,2) 11(10,0) 12(10,2) 13(12,0) 14(12,2)
  silkscreen extent -2.29,-1.27 14.22,8.38, body extent -2.32,-0.27 14.33,8.38, height 6.3
455580003 [mm]
  round 2.775 hole 1.85: 1(0,0) 2(4.191,0) 3(8.4,0) 4(0,-4.2) 5(4.2,-4.2) 6(8.4,-4.2)
  round 1.525 hole 3.05 unplated: MH1(0,7.3) MH2(8.4,7.3)
  silkscreen extent -2.7,1.1 11.1,13.9, body extent -3.14,-4.78 11.06,13.86, height 11.53
9181089621 [mm] "Connector; IDC, PCB Transition - 2 Rows, Thru-Hole; 8 Position; Vertical; Pitch 2.54 mm; Body 15.46 x 6.1 x 7.45 mm (LxWxH)"
  rect 1.5x1.5 hole 0.9: 1(-3.81,-1.27)
  round 1.5 hole 0.9: 2(-3.81,1.27) 3(-1.27,-1.27) 4(-1.27,1.27) 5(1.27,-1.27) 6(1.27,1.27) 7(3.81,-1.27) 8(3.81,1.27)
  silkscreen extent -7.73,-3.83 7.73,3.05
ADI-R-8_M [mm] "SOIC, 8-Leads, Body 4.9x3.9mm, Pitch 1.27mm, IPC Low Density"
  oval 2.5x0.7 smd: 1(-2.45,1.905) 2(-2.45,0.635) 3(-2.45,-0.635) 4(-2.45,-1.905) 5(2.45,-1.905) 6(2.45,-0.635) 7(2.45,0.635) 8(2.45,1.905)
  silkscreen extent -2.57,-2.5 0.8,2.93, body extent -2,-2.5 2,2.5, height 1.75
ADI-RU-28_M [mm] "SOP, 28-Leads, Body 9.7x4.4mm, Pitch 0.65mm, IPC Low Density"
  oval 1.85x0.35 smd: 1(-2.925,4.225) 2(-2.925,3.575) 3(-2.925,2.925) 4(-2.925,2.275) 5(-2.925,1.625) 6(-2.925,0.975) 7(-2.925,0.325) 8(-2.925,-0.325) 9(-2.925,-0.975) 10(-2.925,-1.625) 11(-2.925,-2.275) 12(-2.925,-2.925) 13(-2.925,-3.575) 14(-2.925,-4.225) 15(2.925,-4.225) 16(2.925,-3.575) 17(2.925,-2.925) 18(2.925,-2.275) 19(2.925,-1.625) 20(2.925,-0.975) 21(2.925,-0.325) 22(2.925,0.325) 23(2.925,0.975) 24(2.925,1.625) 25(2.925,2.275) 26(2.925,2.925) 27(2.925,3.575) 28(2.925,4.225)
  silkscreen extent -3.05,-4.9 1.6,5.08, body extent -2.25,-4.9 2.25,4.9, height 1.2
AT224-3 [mil] "Mini-Circuits transformer"
  rect 65x30 smd: 1(0,-100) 2(0,-50) 3(0,0) 4(125,0) 6(125,-100)
  silkscreen extent 25,-135 100,-135, body extent 0,-125 125,25, height 150
CA053035 [mil] "Axial film capacitor, Size 0.53\"(L) x 0.35\"(D)"
  round 65 hole 38: 1(0,0) 2(730,0)
  silkscreen extent 40,-175 690,175, body extent 80,-175 650,175, height 360
CAPC0603X33X15NL03T05 [mm] "Chip Capacitor, 2-Leads, Body 0.60x0.30mm, IPC Medium Density"
  rect 0.46x0.42 smd: 1(-0.33,0) 2(0.33,0)
  body extent -0.31,-0.17 0.32,0.16, height 0.33
CC1005-0402 [mm] "Chip Capacitor; Body 1.0 x 0.5 mm (LxW typ)"
  rect 0.9x0.7 smd: 1(-0.65,0) 2(0.65,0)
  body extent -0.52,-0.28 0.52,0.27, height 0.55
CC1608-0603 [mm] "Chip Capacitor; Body 1.6 x 0.8 mm (LxW typ)"
  rect 1.1x1 smd: 1(-0.85,0) 2(0.85,0)
  silkscreen extent -1.7,-0.4 -1.7,0.4, body extent -0.87,-0.48 0.87,0.48, height 0.87
CC2013-0805 [mm] "Chip Capacitor; Body 2.0 x 1.3 mm (LxW typ)"
  rect 1.15x1.4 smd: 1(-0.975,0) 2(0.975,0)
  silkscreen extent -1.85,-0.6 -1.85,0.6, body extent -1.1,-0.73 1.1,0.72, height 0.88
CC3216-1206 [mm] "Chip Capacitor; Body 3.2 x 1.6 mm (LxW typ)"
  rect 1.6x1.8 smd: 1(-1.4,0) 2(1.4,0)
  silkscreen extent -0.3,-0.8 0.3,0.8, body extent -1.85,-0.97 1.85,0.97, height 0.88
CL2520-1008 [mm] "Chip Inductor; Body 2.54 x 2.0 mm (LxW typ)"
  rect 1.3x2.1 smd: 1(-1.3,0) 2(1.3,0)
  silkscreen extent -2.25,-1 -2.25,1, body extent -1.46,-1.39 1.46,1.4, height 2.02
